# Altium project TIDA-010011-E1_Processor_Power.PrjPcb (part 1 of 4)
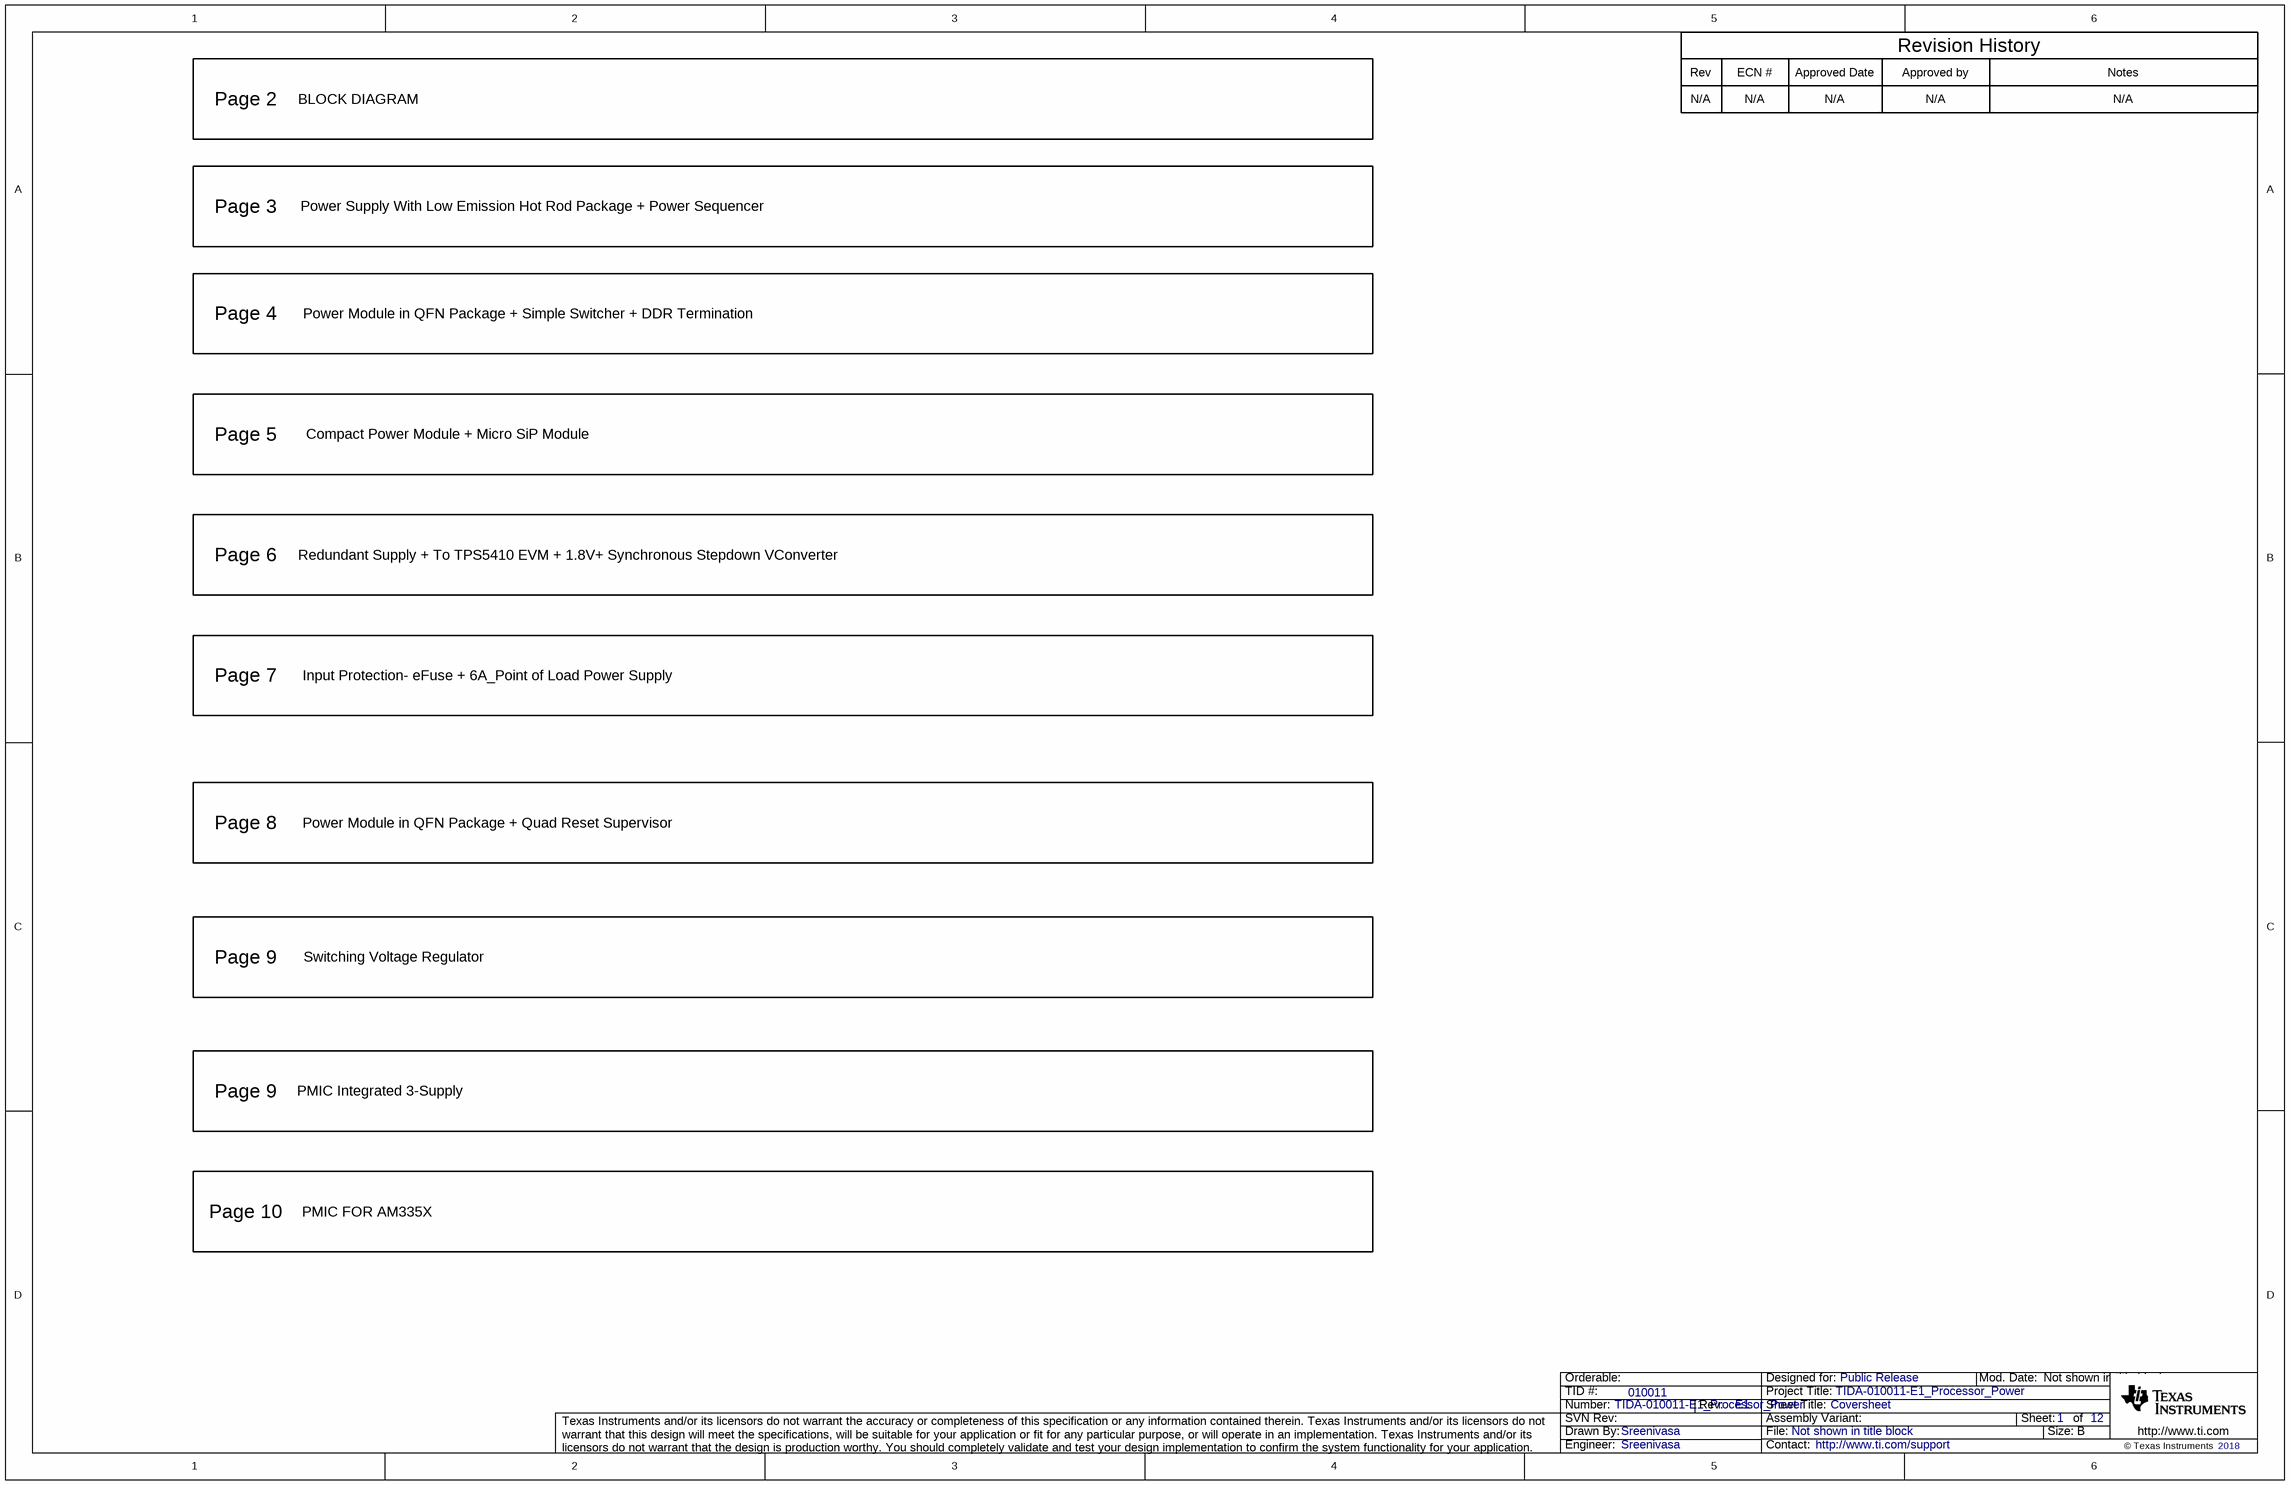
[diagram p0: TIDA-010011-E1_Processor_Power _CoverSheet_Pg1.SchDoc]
CopyrightYear: 2018; PCB_Layout: Avinash N; PCB_Rev: E1; PRJ_Customer: Public Release; PRJ_Engineer: Sreenivasa; PRJ_Number: TIDA-010011-E1_Processor_Power; PRJ_Title: TIDA-010011-E1_Processor_Power; SCH_Rev: E1; TechSupport: http://www.ti.com/support; TID: 010011
12 sheets, 636 parts. Net scope: global (net labels, ports and power ports of the same name join across sheets).
Board file: TIDA-010011-E1_Processor_Power.PcbDoc
Sheets:
  TIDA-010011-E1_Processor_Power _CoverSheet_Pg1.SchDoc
  TIDA-010011-E1_Processor_Power _ Block Diagram_Pg2.SchDoc
  TIDA-010011-E1_Processor_Power _Pg3.SchDoc
  TIDA-010011-E1_Processor_Power _Pg4.SchDoc
  TIDA-010011-E1_Processor_Power _Pg5.SchDoc
  TIDA-010011-E1_Processor_Power _Pg6.SchDoc
  TIDA-010011-E1_Processor_Power _Pg7.SchDoc
  TIDA-010011-E1_Processor_Power _Pg8.SchDoc
  TIDA-010011-E1_Processor_Power _Pg9.SchDoc
  TIDA-010011-E1_Processor_Power _Pg10.SchDoc
  TIDA-010011-E1_Processor_Power _Pg11.SchDoc
  TIDA-010011-E1_Processor_Power _EVM_Hardware_Pg11.SchDoc

## Sheet TIDA-010011-E1_Processor_Power _CoverSheet_Pg1.SchDoc: Coversheet
size 431 x 279 mm; Date: Not shown in title block; ApprovedBy: Not shown in title block; CheckedBy: Not shown in title block; Author: Not shown in title block; CompanyName: Not shown in title block; DrawnBy: Sreenivasa; Engineer: Not shown in title block; Organization: Not shown in title block; Address1: Not shown in title block; Address2: Not shown in title block; Address3: Not shown in title block; Address4: Not shown in title block; DocumentNumber: 1; Revision: Use project parameter SCH_Rev; SheetNumber: 1; SheetTotal: 12; PageSetup: Record=PageOptions¦CenterHorizontal=True¦CenterVertical=True¦PrintScale=1.00¦XCorrection=1.00¦YCorrection=1.00¦PrintKind=0¦BorderSize=5000000¦LeftOffset=0¦BottomOffset=0¦Orientation=2¦PaperLength=1000¦PaperWidth=1000¦Scale=100¦PaperSource=15¦PrintQuality=600¦MediaType=1¦DitherType=10¦PaperKind=Letter¦PrintScaleMode=1

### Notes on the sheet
- Page 2
- BLOCK DIAGRAM
- Rev
- N/A
- ECN #
- Approved Date
- Approved by
- Revision History
- Notes
- Page 3
- Power Supply With Low Emission Hot Rod Package + Power Sequencer
- Page 4
- Power Module in QFN Package + Simple Switcher + DDR Termination
- Page 5
- Compact Power Module + Micro SiP Module
- Page 6
- Redundant Supply + To TPS5410 EVM + 1.8V+ Synchronous Stepdown VConverter
- Page 7
- Input Protection- eFuse + 6A_Point of Load Power Supply
- Page 8
- Power Module in QFN Package + Quad Reset Supervisor
- Page 9
- Switching Voltage Regulator
- PMIC Integrated 3-Supply
- Page 10
- PMIC FOR AM335X

## Sheet TIDA-010011-E1_Processor_Power _ Block Diagram_Pg2.SchDoc: Block Diagram
size 431 x 279 mm; Date: Not shown in title block; ApprovedBy: Not shown in title block; CheckedBy: Not shown in title block; Author: Not shown in title block; CompanyName: Not shown in title block; DrawnBy: Sreenivasa; Engineer: Sreenivasa; Organization: Not shown in title block; Address1: Not shown in title block; Address2: Not shown in title block; Address3: Not shown in title block; Address4: Not shown in title block; DocumentNumber: 1; Revision: Use project parameter SCH_Rev; SheetNumber: 2; SheetTotal: 12; PageSetup: Record=PageOptions¦CenterHorizontal=True¦CenterVertical=True¦PrintScale=1.00¦XCorrection=1.00¦YCorrection=1.00¦PrintKind=0¦BorderSize=5000000¦LeftOffset=0¦BottomOffset=0¦Orientation=2¦PaperLength=1000¦PaperWidth=1000¦Scale=100¦PaperSource=15¦PrintQuality=600¦MediaType=1¦DitherType=10¦PaperKind=Letter¦PrintScaleMode=1
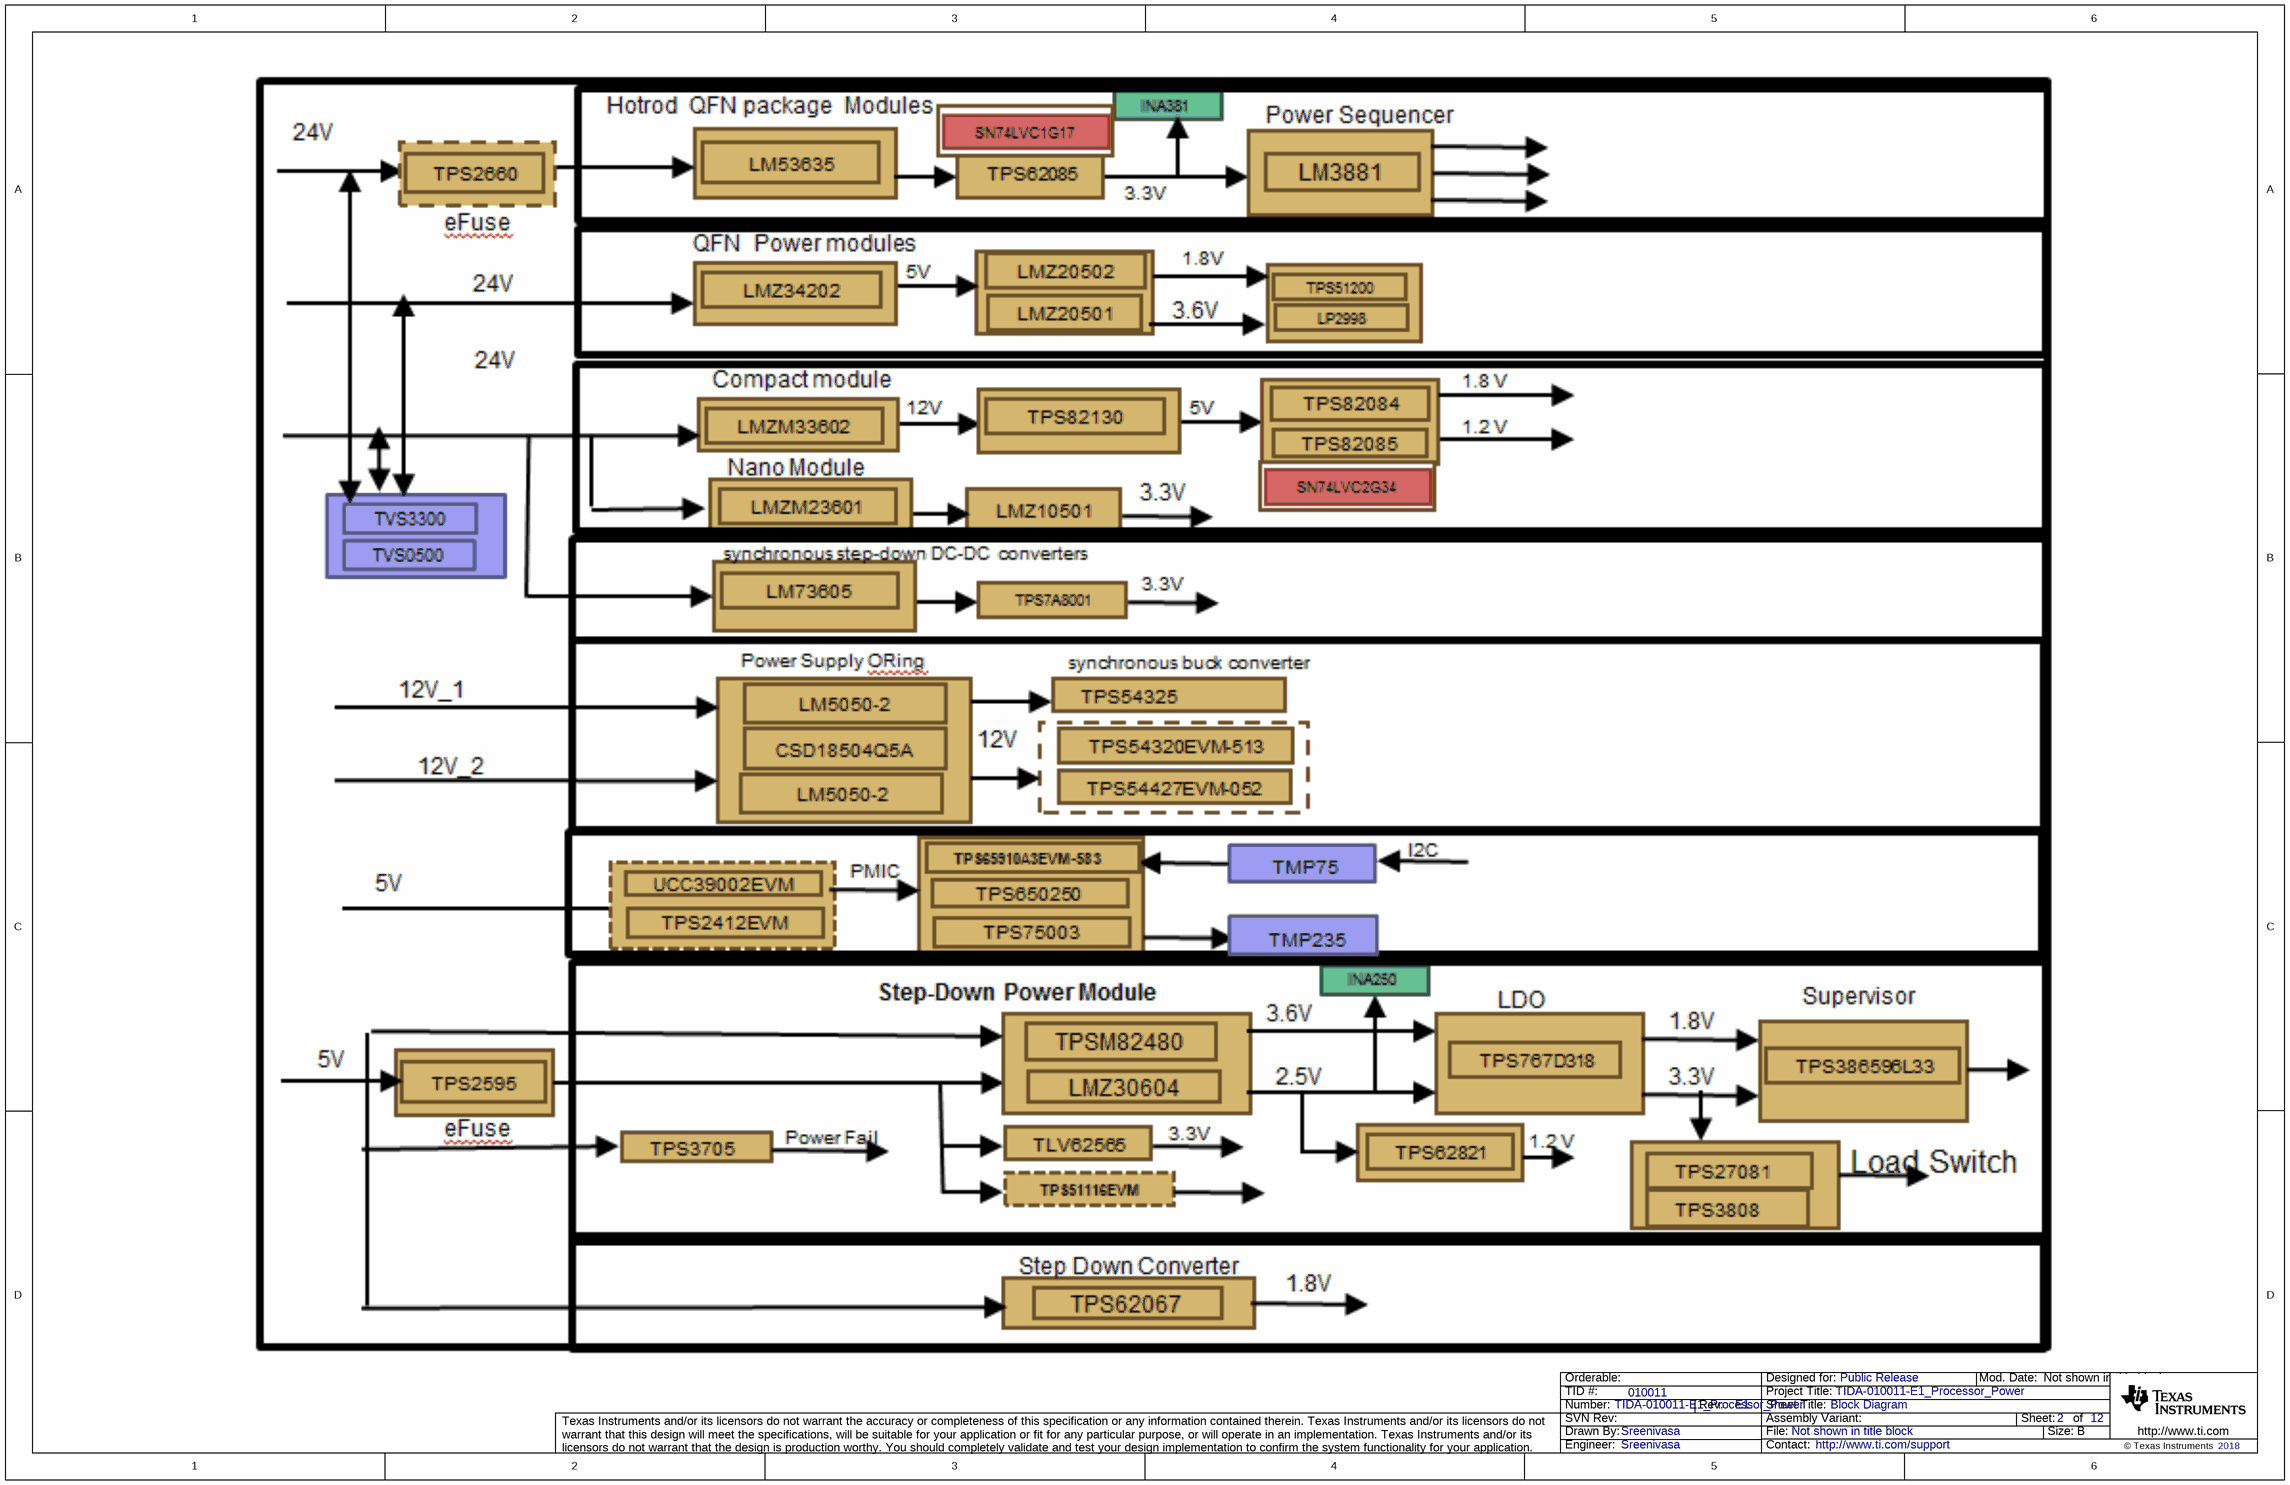
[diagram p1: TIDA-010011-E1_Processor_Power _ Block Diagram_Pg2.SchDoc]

## Sheet TIDA-010011-E1_Processor_Power _Pg3.SchDoc: +24V_HOT RED PACKAGE
size 431 x 279 mm; Date: Not shown in title block; ApprovedBy: Not shown in title block; CheckedBy: Not shown in title block; Author: Not shown in title block; CompanyName: Not shown in title block; DrawnBy: Sreenivasa; Engineer: Not shown in title block; Organization: Not shown in title block; Address1: Not shown in title block; Address2: Not shown in title block; Address3: Not shown in title block; Address4: Not shown in title block; DocumentNumber: 1; Revision: Use project parameter SCH_Rev; SheetNumber: 3; SheetTotal: 12; PageSetup: Record=PageOptions¦CenterHorizontal=True¦CenterVertical=True¦PrintScale=0.62¦XCorrection=1.00¦YCorrection=1.00¦PrintKind=0¦BorderSize=5000000¦LeftOffset=0¦BottomOffset=0¦Orientation=2¦PaperLength=1000¦PaperWidth=1000¦Scale=100¦PaperSource=15¦PrintQuality=600¦MediaType=1¦DitherType=10¦PrintScaleMode=1¦PaperKind=Letter
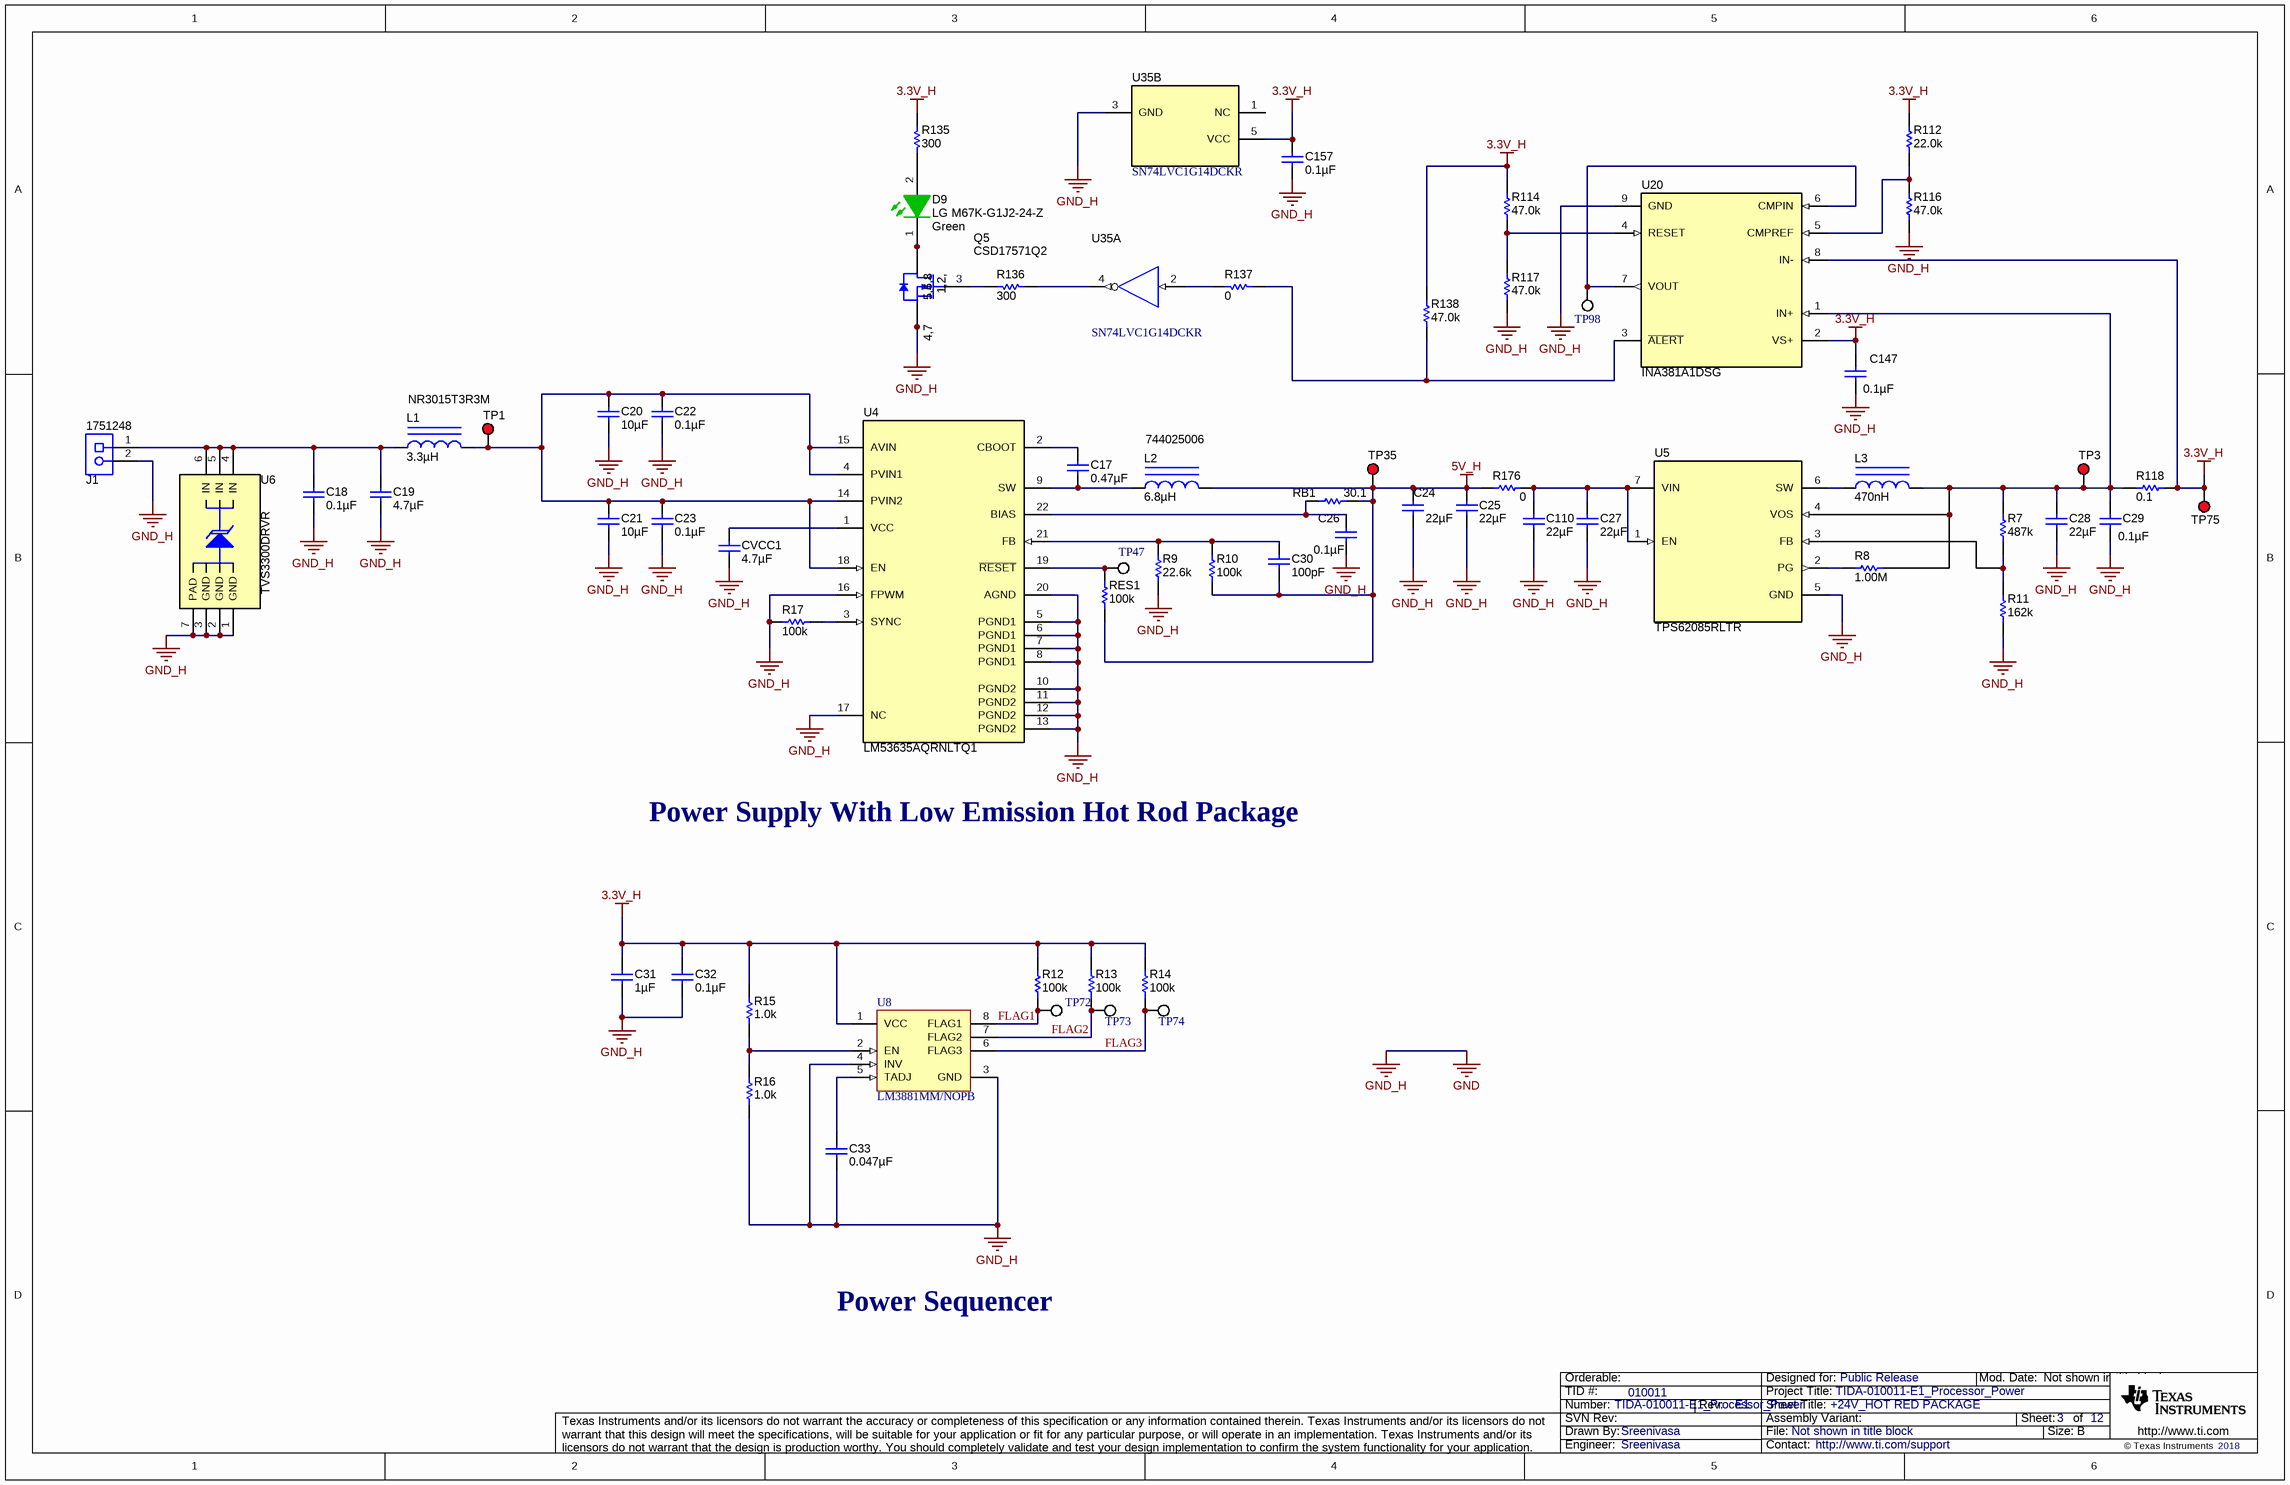
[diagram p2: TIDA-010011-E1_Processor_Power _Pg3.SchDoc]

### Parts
C17  ValueDisplayed: 0.47µF  [0603]  (hidden comment: GCM188R71E474KA64D)
C18  ValueDisplayed: 0.1µF  [0805_HV]  (hidden comment: C2012X7R2A104K125AA)
C19  ValueDisplayed: 4.7µF  [1206]  (hidden comment: C3216X7R1V475K085AC)
C20  ValueDisplayed: 10µF  [1206_180]  (hidden comment: GRM31CR71E106KA12L)
C21  ValueDisplayed: 10µF  [1206_180]  (hidden comment: GRM31CR71E106KA12L)
C22  ValueDisplayed: 0.1µF  [0805_HV]  (hidden comment: C2012X7R2A104K125AA)
C23  ValueDisplayed: 0.1µF  [0805_HV]  (hidden comment: C2012X7R2A104K125AA)
C24  ValueDisplayed: 22µF  [1210_280]  (hidden comment: CGA6P1X7R1C226M250AC)
C25  ValueDisplayed: 22µF  [1210_280]  (hidden comment: CGA6P1X7R1C226M250AC)
C26  ValueDisplayed: 0.1µF  [0603L]  (hidden comment: GRM188R71H104KA93D)
C27  ValueDisplayed: 22µF  [0805_HV]  (hidden comment: JMK212BJ226KG-T)
C28  ValueDisplayed: 22µF  [0805_HV]  (hidden comment: JMK212BJ226KG-T)
C29  ValueDisplayed: 0.1µF  [0603L]  (hidden comment: GRM188R71H104KA93D)
C30  ValueDisplayed: 100pF  [0603]  (hidden comment: 06035A101JAT2A)
C31  ValueDisplayed: 1µF  [0603]  (hidden comment: CL10B105KQ8NNNC)
C32  ValueDisplayed: 0.1µF  [0603]  (hidden comment: 0603ZC104KAT2A)
C33  ValueDisplayed: 0.047µF  [0805_HV]  (hidden comment: 08055C473KAT2A)
C110  ValueDisplayed: 22µF  [0805_HV]  (hidden comment: JMK212BJ226KG-T)
C147  ValueDisplayed: 0.1µF  [0603L]  (hidden comment: GRM188R71H104KA93D)
C157  ValueDisplayed: 0.1µF  [0603]  (hidden comment: GMK107BJ104KAHT)
CVCC1  ValueDisplayed: 4.7µF  [0603]  (hidden comment: CGB3B1X5R1A475K055AC)
D9  LG M67K-G1J2-24-Z  value Green  [LG_M67K_Green]
J1  1751248  [CONN_1751248]
L1  NR3015T3R3M  ValueDisplayed: 3.3µH  [NR3015]
L2  744025006  ValueDisplayed: 6.8µH  [WE-TPC_2828]
L3  ValueDisplayed: 470nH  [VLS2012ET]  (hidden comment: VLS2012ET-R47N)
Q5  CSD17571Q2  [DQK0006C]
R7  ValueDisplayed: 487k  [0402]  (hidden comment: CRCW0402487KFKED)
R8  ValueDisplayed: 1.00M  [0402L]  (hidden comment: RC0402FR-071ML)
R9  ValueDisplayed: 22.6k  [0402]  (hidden comment: CRCW040222K6FKED)
R10  ValueDisplayed: 100k  [0402]  (hidden comment: CRCW0402100KFKED)
R11  ValueDisplayed: 162k  [0603L]  (hidden comment: RC0603FR-07162KL)
R12  ValueDisplayed: 100k  [0805_HV]  (hidden comment: ERJ-6ENF1003V)
R13  ValueDisplayed: 100k  [0805_HV]  (hidden comment: ERJ-6ENF1003V)
R14  ValueDisplayed: 100k  [0805_HV]  (hidden comment: ERJ-6ENF1003V)
R15  ValueDisplayed: 1.0k  [0603]  (hidden comment: CRCW06031K00JNEA)
R16  ValueDisplayed: 1.0k  [0603]  (hidden comment: CRCW06031K00JNEA)
R17  ValueDisplayed: 100k  [0402]  (hidden comment: CRCW0402100KFKED)
R112  ValueDisplayed: 22.0k  [0603]  (hidden comment: ERJ-3EKF2202V)
R114  ValueDisplayed: 47.0k  [0603]  (hidden comment: RG1608P-473-B-T5)
R116  ValueDisplayed: 47.0k  [0603]  (hidden comment: RG1608P-473-B-T5)
R117  ValueDisplayed: 47.0k  [0603]  (hidden comment: RG1608P-473-B-T5)
R118  ValueDisplayed: 0.1  [0805_HV]  (hidden comment: ERJ-6RSJR10V)
R135  ValueDisplayed: 300  [0603]  (hidden comment: CRCW0603300RJNEA)
R136  ValueDisplayed: 300  [0603]  (hidden comment: CRCW0603300RJNEA)
R137  ValueDisplayed: 0  [0603]  (hidden comment: RMCF0603ZT0R00)
R138  ValueDisplayed: 47.0k  [0603]  (hidden comment: RG1608P-473-B-T5)
R176  ValueDisplayed: 0  [0805_HV]  (hidden comment: CRCW08050000Z0EA)
RB1  ValueDisplayed: 30.1  [0402]  (hidden comment: CRCW040230R1FKED)
RES1  ValueDisplayed: 100k  [0603]  (hidden comment: RG1608P-104-B-T5)
TP1  (no value)  [Keystone5000]
TP3  (no value)  [Keystone5000]
TP35  (no value)  [Keystone5000]
TP47  5002  [Keystone5002]  (value not drawn)
TP72  5002  [Keystone5002]  (value not drawn)
TP73  5002  [Keystone5002]  (value not drawn)
TP74  5002  [Keystone5002]  (value not drawn)
TP75  (no value)  [Keystone5000]
TP98  5002  [Keystone5002]  (value not drawn)
U4  LM53635AQRNLTQ1  [RNL0022A_NV]
U5  TPS62085RLTR  [RLT0007A]
U6  TVS3300DRVR  [DRV0006A]
U8  LM3881MM/NOPB  [MUA08A_N]
U20  INA381A1DSG  [DSG0008A]
U35  SN74LVC1G14DCKR  [DCK0005A_N]  (parts A,B of 2)

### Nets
3.3V_H: C31.1 C32.1 C147.1 C157.1 R12.2 R13.2 R14.2 R15.2 R112.2 R114.1 R118.1 R135.2 R138.1 TP75.1 U8.1(VCC) U20.2(VS+) U20.8(IN-) U35.5(VCC)
5V_H: C24.1 C25.1 C30.2 L2.2 R10.1 R176.2 RB1.2 RES1.1 TP35.1
GND: C18.2 C19.2 C20.2 C21.2 C22.2 C23.2 C24.2 C25.2 C26.2 C27.2 C28.2 C29.2 C31.2 C32.2 C33.2 C110.2 C147.2 C157.2 CVCC1.2 J1.2 Q5.4(S) Q5.7(S) R9.1 R11.1 R16.1 R17.2 R116.1 R117.1 U4.5(PGND1) U4.6(PGND1) U4.7(PGND1) U4.8(PGND1) U4.10(PGND2) U4.11(PGND2) U4.12(PGND2) U4.13(PGND2) U4.16(FPWM) U4.17(NC) U4.20(AGND) U5.5(GND) U6.1(GND) U6.2(GND) U6.3(GND) U6.7(PAD) U8.3(GND) U8.4(INV) U20.9(GND) U35.3(GND)  [also labelled GND_H]
FLAG1: R12.1 TP72.1 U8.8(FLAG1)
FLAG2: R13.1 TP73.1 U8.7(FLAG2)
FLAG3: R14.1 TP74.1 U8.6(FLAG3)
NetC17_1: C17.1 U4.2(CBOOT)
NetC17_2: C17.2 L2.1 U4.9(SW)
NetC18_1: C18.1 C19.1 J1.1 L1.1 U6.4(IN) U6.5(IN) U6.6(IN)
NetC20_1: C20.1 C21.1 C22.1 C23.1 L1.2 TP1.1 U4.4(PVIN1) U4.14(PVIN2) U4.15(AVIN) U4.18(EN)
NetC26_1: C26.1 RB1.1 U4.22(BIAS)
NetC27_1: C27.1 C110.1 R176.1 U5.1(EN) U5.7(VIN)
NetC28_1: C28.1 C29.1 L3.2 R7.2 R8.2 R118.2 TP3.1 U5.4(VOS) U20.1(IN+)
NetC30_1: C30.1 R9.2 R10.2 U4.21(FB)
NetC33_1: C33.1 U8.5(TADJ)
NetCVCC1_1: CVCC1.1 U4.1(VCC)
NetD9_1: D9.1(K) Q5.1(D) Q5.2(D) Q5.5(D) Q5.6(D) Q5.8(D)
NetD9_2: D9.2(A) R135.1
NetL3_1: L3.1 U5.6(SW)
NetQ5_3: Q5.3(G) R136.1
NetR7_1: R7.1 R11.2 U5.3(FB)
NetR8_1: R8.1 U5.2(PG)
NetR15_1: R15.1 R16.2 U8.2(EN)
NetR17_1: R17.1 U4.3(SYNC)
NetR112_1: R112.1 R116.2 U20.5(CMPREF)
NetR114_2: R114.2 R117.2 U20.4(RESET)
NetR136_2: R136.2 U35.4(Y)
NetR137_1: R137.1 R138.2 U20.3(~{ALERT})
NetR137_2: R137.2 U35.2(A)
NetRES1_2: RES1.2 TP47.1 U4.19(~{RESET})
NetTP98_1: TP98.1 U20.6(CMPIN) U20.7(VOUT)

Not connected (* = marked no-connect by the designer): U35 1(NC)

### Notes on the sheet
- Power Supply With Low Emission Hot Rod Package
- Power Sequencer

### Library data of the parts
C17 = GCM188R71E474KA64D: CAP, CERM, 0.47 µF, 25 V, +/- 10%, X7R, AEC-Q200 Grade 1, 0603; Manufacturer: MuRata; Polarized: N; CompType: Capacitor; Value: 0.47uF; U/M: EA; Cap_F: 0.00000047; Tolerance_%: 10; Value1: Unknown; VDC_V: 25; Value2: 25V; TaMin_C: -55; TaMax_C: 125; SizeArea_mm2: 1.28; SizeAreaWB_mm2: 4.68; SizeX_mm: 1.6; SizeY_mm: 0.8; SizeZ_mm: 1; AEC Category: Q200; AEC Qualified: Y
C18 C22 C23 = C2012X7R2A104K125AA: CAP, CERM, 0.1 µF, 100 V, +/- 10%, X7R, 0805; Manufacturer: TDK; Polarized: N; CompType: Capacitor; Value: 0.1uF; U/M: EA; Cap_F: 0.0000001; Tolerance_%: 10; ESR_ohm: 0.020726; Value1: 0.020726 ohm; VDC_V: 100; Value2: 100V; IRMS_A: 1.456; TaMin_C: -55; TaMax_C: 125; Cap_Case: 0805; SizeArea_mm2: 2.5; SizeAreaWB_mm2: 6.75; SizeX_mm: 2; SizeY_mm: 1.25; SizeZ_mm: 1.45; AEC Category: Q200
C19 = C3216X7R1V475K085AC: CAP, CERM, 4.7 µF, 35 V, +/- 10%, X7R, 1206; Manufacturer: TDK; Polarized: N; CompType: Capacitor; Value: 4.7uF; U/M: EA; Cap_F: 0.0000047; Tolerance_%: 10; ESR_ohm: 0.003785; Value1: 0.003785 ohm; VDC_V: 35; Value2: 35V; IRMS_A: 3.73011; TaMin_C: -55; TaMax_C: 125; SizeArea_mm2: 5.12; SizeAreaWB_mm2: 10.92; SizeX_mm: 3.2; SizeY_mm: 1.6; SizeZ_mm: 1.35; AEC Category: Q200
C20 C21 = GRM31CR71E106KA12L: CAP, CERM, 10 µF, 25 V, +/- 10%, X7R, 1206; Manufacturer: MuRata; Polarized: N; CompType: Capacitor; Value: 10uF; U/M: EA; Cap_F: 0.00001; Tolerance_%: 10; Value1: Unknown; VDC_V: 25; Value2: 25V; TaMin_C: -55; TaMax_C: 125; Cap_Case: 2220; SizeArea_mm2: 5.12; SizeAreaWB_mm2: 10.92; SizeX_mm: 3.2; SizeY_mm: 1.6; SizeZ_mm: 1.8; AEC Category: Q200
C24 C25 = CGA6P1X7R1C226M250AC: CAP, CERM, 22 µF, 16 V, +/- 20%, X7R, AEC-Q200 Grade 1, 1210; Manufacturer: TDK; Polarized: N; CompType: Capacitor; Value: 22uF; U/M: EA; Cap_F: 0.000022; Tolerance_%: 20; ESR_ohm: 0.002582; Value1: 0.002582 ohm; VDC_V: 16; Value2: 16V; IRMS_A: 4.57562; TaMin_C: -55; TaMax_C: 125; SizeArea_mm2: 8; SizeAreaWB_mm2: 14.7; SizeX_mm: 3.2; SizeY_mm: 2.5; SizeZ_mm: 2.8; AEC Category: Q200; AEC Qualified: Y; AEC Grade: 1
C26 C29 C147 = GRM188R71H104KA93D: CAP, CERM, 0.1 µF, 50 V, +/- 10%, X7R, 0603; Manufacturer: MuRata; Polarized: N; CompType: Capacitor; Value: 0.1uF; U/M: EA; Cap_F: 0.0000001; Tolerance_%: 10; Value1: Unknown; VDC_V: 50; Value2: 50V; TaMin_C: -55; TaMax_C: 125; Cap_Case: 0603
C27 C28 C110 = JMK212BJ226KG-T: CAP, CERM, 22 µF, 6.3 V,+/- 10%, X5R, 0805; Manufacturer: Taiyo Yuden; Polarized: N; CompType: Capacitor; Value: 22uF; U/M: EA; Cap_F: 0.000022; Tolerance_%: 10; ESR_ohm: 0.002; Value1: 0.002 ohm; VDC_V: 6.3; Value2: 6.3V; TaMin_C: -55; TaMax_C: 85; Cap_Case: 0805; AEC Category: Q200; SizeArea_mm2: 2.5; SizeAreaWB_mm2: 6.75; SizeX_mm: 2; SizeY_mm: 1.25; SizeZ_mm: 1.45; Green_Lifecycle: Not Set; Green_REACh: Incomplete
C30 = 06035A101JAT2A: CAP, CERM, 100 pF, 50 V,+/- 5%, C0G/NP0, 0603; Manufacturer: AVX; Polarized: N; CompType: Capacitor; Value: 100pF; U/M: EA; Cap_F: 0.0000000001; Tolerance_%: 5; ESR_ohm: 0.119; Value1: 0.119 ohm; VDC_V: 50; Value2: 50V; TaMin_C: -55; TaMax_C: 125; SizeArea_mm2: 1.28; SizeAreaWB_mm2: 4.68; SizeX_mm: 1.6; SizeY_mm: 0.8; SizeZ_mm: 1; AEC Category: Q200; Green_Lifecycle: Active; Green_REACh: Passed
C31 = CL10B105KQ8NNNC: CAP, CERM, 1 µF, 6.3 V, +/- 10%, X7R, 0603; Manufacturer: Samsung Electro-Mechanics; Polarized: N; CompType: Capacitor; Value: 1uF; U/M: EA; Cap_F: 0.000001; Tolerance_%: 10; Value1: Unknown; VDC_V: 6.3; Value2: 6.3V; TaMin_C: -55; TaMax_C: 125; SizeArea_mm2: 1.28; SizeAreaWB_mm2: 4.68; SizeX_mm: 1.6; SizeY_mm: 0.8; SizeZ_mm: 1; AEC Category: Q200
C32 = 0603ZC104KAT2A: CAP, CERM, 0.1 µF, 10 V, +/- 10%, X7R, 0603; Manufacturer: AVX; Polarized: N; CompType: Capacitor; Value: 0.1uF; U/M: EA; Cap_F: 0.0000001; Tolerance_%: 10; Value1: Unknown; Value2: 10V; TaMin_C: -55; TaMax_C: 125; SizeArea_mm2: 1.28; SizeAreaWB_mm2: 4.68; SizeX_mm: 1.6; SizeY_mm: 0.8; SizeZ_mm: 1; AEC Category: Q200
C33 = 08055C473KAT2A: CAP, CERM, 0.047 µF, 50 V,+/- 10%, X7R, 0805; Manufacturer: AVX; Polarized: N; CompType: Capacitor; Value: 0.047uF; U/M: EA; Cap_F: 0.000000047; Tolerance_%: 10; ESR_ohm: 0.035; Value1: 0.035 ohm; VDC_V: 50; Value2: 50V; TaMin_C: -55; TaMax_C: 125; Cap_Case: 0805; SizeArea_mm2: 2.5; SizeAreaWB_mm2: 6.75; SizeX_mm: 2; SizeY_mm: 1.25; SizeZ_mm: 1.45; AEC Category: Q200; Green_Lifecycle: Active; Green_REACh: Passed
C157 = 06033C104JAT2A: 0.1µF ±10% 35V Ceramic Capacitor X5R 0603; Manufacturer: Taiyo Yuden; Polarized: N; Value: 0.1uF; U/M: EA; Cap_F: 0.0000001; Tolerance_%: 5; ESR_ohm: 0.05; Value1: 0.05 ohm; VDC_V: 25; Value2: 25V; TempCo: X7R; TaMin_C: -55; TaMax_C: 125; SizeArea_mm2: 1.28; SizeAreaWB_mm2: 4.68; SizeX_mm: 1.6; SizeY_mm: 0.8; SizeZ_mm: 1; AEC Category: Q200
CVCC1 = CGB3B1X5R1A475K055AC: CAP, CERM, 4.7 µF, 10 V,+/- 10%, X5R, 0603; Manufacturer: TDK; Polarized: N; CompType: Capacitor; Value: 4.7uF; U/M: EA; Cap_F: 0.0000047; Tolerance_%: 10; Value2: 10V; TaMin_C: -55; TaMax_C: 85; SizeArea_mm2: 1.28; SizeAreaWB_mm2: 4.68; SizeX_mm: 1.6; SizeY_mm: 0.8; SizeZ_mm: 1; AEC Category: Q200; Green_Lifecycle: Active; Green_REACh: Passed
D9 = LG M67K-G1J2-24-Z: LED, Green, SMD; Manufacturer: OSRAM; SymbolCreator: Altium; Type: AlInGaP; Vf_V: 1.8; Value2: 1.8V; Io_A: 0.002; Vr_V: 12; Tjmax_C: 125; Value1: W; Angle: 120; U/M: EA
J1 = 1751248: Conn Term Block, 2POS, 3.5mm, TH; Manufacturer: Phoenix Contact; CompType: Terminal Block; SymbolCreator: a0412235
L1 = NR3015T3R3M: Inductor, Wirewound, Ferrite, 3.3 µH, 1.21 A, 0.096 ohm, AEC-Q200 Grade 2, SMD; Manufacturer: Taiyo Yuden; Value: 3.3uH; Imax_A: 1.21; DCR_ohm: 0.096; Value2: 1.21A; Ind_H: 3.3E-6; Irms: 1.23A @ 40C rise; Isat: 1.21A @ 30% inductance drop; SizeAreaWB_mm2: 16; SizeArea_mm2: 9; SizeX_mm: 3; SizeZ_mm: 1.5; AEC Category: Q200; AEC Qualified: Y; AEC Grade: 2
L2 = 744025006: Inductor, Shielded Drum Core, Ferrite, 6.8 µH, 1.1 A, 0.142 ohm, SMD; Manufacturer: Wurth Elektronik; Value: 6.8uH; Ind_H: 6.8E-6; Imax_A: 1.1; Irms: 1.1A @ 40C rise; Isat: 1.3A @ 35% inductance drop; DCR_ohm: 0.142; Value2: 1.1A; SizeAreaWB_mm2: 14.44; SizeArea_mm2: 7.84; SizeX_mm: 2.8; SizeZ_mm: 3; AEC Category: Q200
L3 = VLS2012ET-R47N: Inductor, Shielded Drum Core, Ferrite, 470 nH, 2 A, 0.059 ohm, SMD; Manufacturer: TDK; Value: 470nH; Ind_H: 470.0E-9; Imax_A: 2; Irms: 2A @ 40C rise; Isat: 2.25A @ 30% inductance drop; DCR_ohm: 0.059; Value2: 2A; AEC Category: Q200
Q5 = CSD17571Q2: MOSFET, N-CH, 30 V, 22 A, DQK0006C (WSON-6); Manufacturer: Texas Instruments; Alternate Manufacturer: None; U/M: EA; ChType: N; Value: 30V; VdsMax_V: 30; Value1: 0.029 ohm; Rdson45_ohm: 0.029; Value2: 2.4 nC; QgTyp_nC: 2.4; Vgs_V: 20; IdsMax_A: 22; SizeAreaWB_mm2: 9; SizeArea_mm2: 4; SizeX_mm: 2; SizeZ_mm: 0.8; AEC Category: Q101
R7 = CRCW0402487KFKED: RES, 487 k, 1%, 0.063 W, 0402; Manufacturer: Vishay-Dale; CompType: Resistor; Value: 487k; Res_ohm: 487000; Tolerance_%: 1; Power_W: 0.063; Value2: 0.063W; VDC_V: 50; TempCo: 100 ppm/C; SizeArea_mm2: 0.5; SizeZ_mm: 0.6; EIA_Code: E96; U/M: EA; AEC Category: Q200; Green_Lifecycle: Active; Green_REACh: Passed
R8 = RC0402FR-071ML: RES, 1.00 M, 1%, 0.063 W, 0402; Manufacturer: Yageo America; CompType: Resistor; Value: 1.00Meg; Res_ohm: 1000000; Value_Code: 1M00; Tolerance_%: 1; Power_W: 0.063; Value2: 0.063W; TempCo: 100 ppm/C; EIA_Code: E96; U/M: EA; AEC Category: Q200; SizeArea_mm2: 0.5; SizeZ_mm: 0.6; Green_Lifecycle: Active; Green_REACh: Passed
R9 = CRCW040222K6FKED: RES, 22.6 k, 1%, 0.063 W, 0402; Manufacturer: Vishay-Dale; CompType: Resistor; Value: 22.6k; Res_ohm: 22600; Value_Code: 22k6; Tolerance_%: 1; Power_W: 0.063; Value2: 0.063W; VDC_V: 50; TempCo: 100 ppm/C; SizeArea_mm2: 0.5; SizeZ_mm: 0.6; EIA_Code: E96; U/M: EA; AEC Category: Q200
R10 R17 = CRCW0402100KFKED: RES, 100 k, 1%, 0.063 W, 0402; Manufacturer: Vishay-Dale; CompType: Resistor; Value: 100k; Res_ohm: 100000; Tolerance_%: 1; Power_W: 0.063; Value2: 0.063W; VDC_V: 50; TempCo: 100 ppm/C; SizeArea_mm2: 0.5; SizeZ_mm: 0.6; EIA_Code: E96; U/M: EA; AEC Category: Q200
R11 = RC0603FR-07162KL: RES, 162 k, 1%, 0.1 W, 0603; Manufacturer: Yageo America; CompType: Resistor; Value: 162k; Res_ohm: 162000; Tolerance_%: 1; Power_W: 0.1; Value2: 0.1W; VDC_V: 150; TempCo: 200 ppm/C; EIA_Code: E96; U/M: EA; AEC Category: Q200; SizeArea_mm2: 1.28; SizeX_mm: 1.6; SizeY_mm: 0.8; Green_Lifecycle: Active; Green_REACh: Passed
R12-R14 = ERJ-6ENF1003V: RES, 100 k, 1%, 0.125 W, 0805; Manufacturer: Panasonic; CompType: Resistor; Value: 100k; Res_ohm: 100000; Tolerance_%: 1; Power_W: 0.125; Value2: 0.125W; TempCo: 100 ppm/C; SizeArea_mm2: 2.5; SizeX_mm: 2; SizeY_mm: 1.25; SizeZ_mm: 1.45; EIA_Code: E96; U/M: EA; AEC Category: Q200
R15 R16 = CRCW06031K00JNEA: RES, 1.0 k, 5%, 0.1 W, 0603; Manufacturer: Vishay-Dale; CompType: Resistor; Value: 1.0k; Res_ohm: 1000; Value_Code: 1k00; Tolerance_%: 5; Power_W: 0.1; Value2: 0.1W; VDC_V: 75; TempCo: 200 ppm/C; SizeArea_mm2: 1.28; SizeX_mm: 1.6; SizeY_mm: 0.8; SizeZ_mm: 1; EIA_Code: E24; U/M: EA; AEC Category: Q200; Green_Lifecycle: Active; Green_REACh: Passed
R112 = ERJ-3EKF2202V: RES, 22.0 k, 1%, 0.1 W, AEC-Q200 Grade 0, 0603; Manufacturer: Panasonic; CompType: Resistor; Value: 22.0k; Res_ohm: 22000; Value_Code: 22k0; Tolerance_%: 1; Power_W: 0.1; Value2: 0.1W; VDC_V: 50; TempCo: 100 ppm/C; SizeArea_mm2: 1.28; SizeX_mm: 1.6; SizeY_mm: 0.8; U/M: EA; AEC Category: Q200; AEC Qualified: Y; AEC Grade: 0; Green_Lifecycle: Active; Green_REACh: Passed
R114 R116 R117 R138 = RG1608P-473-B-T5: RES, 47.0 k, 0.1%, 0.1 W, 0603; Manufacturer: Susumu Co Ltd; CompType: Resistor; Value: 47.0k; Res_ohm: 47000; Value_Code: 47k0; Tolerance_%: 0.1; Value2: 0.1W; VDC_V: 75; TempCo: 25 ppm/C; SizeArea_mm2: 1.28; SizeX_mm: 1.6; SizeY_mm: 0.8; SizeZ_mm: 1; EIA_Code: E192; U/M: EA; AEC Category: Q200
R118 = ERJ-6RSJR10V: RES, 0.1, 5%, 0.125 W, 0805; Manufacturer: Panasonic; CompType: Resistor; Value: 0.1; Value_Code: R100; Tolerance_%: 5; Power_W: 0.125; Value2: 0.125W; TempCo: 250 ppm/C; SizeArea_mm2: 2.5; SizeX_mm: 2; SizeY_mm: 1.25; SizeZ_mm: 1.45; EIA_Code: E24; U/M: EA; AEC Category: Q200; Green_Lifecycle: Not Set; Green_REACh: Incomplete
R135 R136 = CRCW0603300RJNEA: RES, 300, 5%, 0.1 W, 0603; Manufacturer: Vishay-Dale; CompType: Resistor; Value: 300; Value_Code: 300R; Tolerance_%: 5; Power_W: 0.1; Value2: 0.1W; VDC_V: 75; TempCo: 200 ppm/C; SizeArea_mm2: 1.28; SizeX_mm: 1.6; SizeY_mm: 0.8; SizeZ_mm: 1; EIA_Code: E24; U/M: EA; AEC Category: Q200
R137 = RMCF0603ZT0R00: RES, 0, 1%, 0.1 W, AEC-Q200 Grade 0, 0603; Manufacturer: Stackpole Electronics Inc; CompType: Resistor; Value: 0; Tolerance_%: 1; Power_W: 0.1; Value2: 0.1W; TempCo: ppm/C; SizeArea_mm2: 1.28; SizeX_mm: 1.6; SizeY_mm: 0.8; U/M: EA; AEC Category: Q200; AEC Qualified: Y
R176 = CRCW08050000Z0EA: RES, 0, 5%, 0.125 W, 0805; Manufacturer: Vishay-Dale; CompType: Resistor; Value: 0; Value_Code: 0000; Tolerance_%: 5; Power_W: 0.125; Value2: 0.125W; VDC_V: 150; TempCo: 200 ppm/C; SizeArea_mm2: 2.5; SizeX_mm: 2; SizeY_mm: 1.25; SizeZ_mm: 1.45; EIA_Code: E24; U/M: EA; AEC Category: Q200; Green_Lifecycle: Active; Green_REACh: Passed
RB1 = CRCW040230R1FKED: RES, 30.1, 1%, 0.063 W, 0402; Manufacturer: Vishay-Dale; CompType: Resistor; Value: 30.1; Value_Code: 30R1; Tolerance_%: 1; Power_W: 0.063; Value2: 0.063W; VDC_V: 50; TempCo: 100 ppm/C; EIA_Code: E96; U/M: EA; AEC Category: Q200; SizeArea_mm2: 0.5; SizeZ_mm: 0.6; Green_Lifecycle: Active; Green_REACh: Passed
RES1 = RG1608P-104-B-T5: RES, 100 k, 0.1%, 0.1 W, 0603; Manufacturer: Susumu Co Ltd; CompType: Resistor; Value: 100k; Res_ohm: 100000; Tolerance_%: 0.1; Value2: 0.1W; VDC_V: 75; TempCo: 25 ppm/C; SizeArea_mm2: 1.28; SizeX_mm: 1.6; SizeY_mm: 0.8; SizeZ_mm: 1; EIA_Code: E192; U/M: EA; AEC Category: Q200
TP1 TP3 TP35 TP75 = 5000: Test Point, Miniature, Red, TH; Manufacturer: Keystone; CompType: Test Point Loop; ContactFinish: Silver
TP47 TP72-TP74 TP98 = 5002: Test Point, Miniature, White, TH; Manufacturer: Keystone; CompType: Test Point Loop; ContactFinish: Silver; Green_Lifecycle: Active; Green_REACh: Passed
U4 = LM53635RNL: C REG BUCK ADJ 3.5A SYNC 22VQFN; Manufacturer: Texas Instruments; SymbolCreator: Altium; SizeArea_mm2: 20; SizeAreaWB_mm2: 42; SizeX_mm: 4; SizeY_mm: 5; SizeZ_mm: 0.9; CompType: IC; U/M: EA
U5 = TPS62085RLTR: 3-A Step-Down Converter with Hiccup Short Circuit Protection in 2x2 QFN Package, RLT0007A; Alternate PartNumber: TPS62085RLTT; Manufacturer: Texas Instruments; SymbolCreator: a0411947; CompType: IC; U/M: EA
U6 = CMP-0013424-7: 33-V Precision Surge Protection Clamp, DRV0006A (WSON-6); Manufacturer: Texas Instruments; Alternate PartNumber: TVS3300DRVT; SizeX_mm: 2; CompType: IC; SizeZ_mm: 0.8; SizeArea_mm2: 4; SizeAreaWB_mm2: 9; U/M: EA
U8 = LM3881MM/NOPB: Power Sequencer, 8-pin MSOP, Pb-Free; Manufacturer: Texas Instruments; PackageTopMarking: ZXTT*STBB; PowerWise: N; CompType: MiscPower
U20 = CMP-0065195-3: 26-V, Low Cost, Zero-Drift, Voltage-Output, Current-Shunt Monitor With Integrated Comparator, DSG0008A (WSON-8); Manufacturer: Texas Instruments; SizeZ_mm: 0.8; SizeX_mm: 2.0; SizeArea_mm2: 4.0; CompType: IC; U/M: EA; SizeAreaWB_mm2: 9.0
U35 = CMP-0051641-4: Single Schmitt-Trigger Inverter, DCK0005A (SOT-SC70-5); Manufacturer: Texas Instruments; Alternate PartNumber: SN74LVC1G14DCKT; Output Drive (IOL/IOH)(Max)(mA): 32/-32; Schmitt Trigger: Yes; Logic: Inverting; Bits(#): 1; Rating: Catalog; tpd @ Nom Voltage(Max)(ns): 11,6.5,5.5,5; Voltage(Nom)(V): 1.8,2.5,3.3,5; Output Type: CMOS; VCC(Min)(V): 1.65; ICC @ Nom Voltage(Max)(mA): 0.01; Input Type: CMOS/TTL; F @ Nom Voltage(Max)(Mhz): 150; VCC(Max)(V): 5.5; 3-State Output: No; AEC Category: Q200; AEC Qualified: N; CompType: IC; Green_Lifecycle: Active; Green_REACh: Passed; SizeAreaWB_mm2: 9.3; SizeArea_mm2: 4.2; SizeX_mm: 2.1; SizeY_mm: 2.0; SizeZ_mm: 1.1

## Sheet TIDA-010011-E1_Processor_Power _Pg4.SchDoc: POWER MODULE QFN_NANO
size 431 x 279 mm; Date: Not shown in title block; ApprovedBy: Not shown in title block; CheckedBy: Not shown in title block; Author: Not shown in title block; CompanyName: Not shown in title block; Engineer: Not shown in title block; Organization: Not shown in title block; Address1: Not shown in title block; Address2: Not shown in title block; Address3: Not shown in title block; Address4: Not shown in title block; DocumentNumber: 1; Revision: Use project parameter SCH_Rev; SheetNumber: 4; SheetTotal: 12; PageSetup: Record=PageOptions¦CenterHorizontal=True¦CenterVertical=True¦PrintScale=1.00¦XCorrection=1.00¦YCorrection=1.00¦PrintKind=0¦BorderSize=5000000¦LeftOffset=0¦BottomOffset=0¦Orientation=2¦PaperLength=1000¦PaperWidth=1000¦Scale=100¦PaperSource=15¦PrintQuality=600¦MediaType=1¦DitherType=10¦PaperKind=Letter¦PrintScaleMode=1
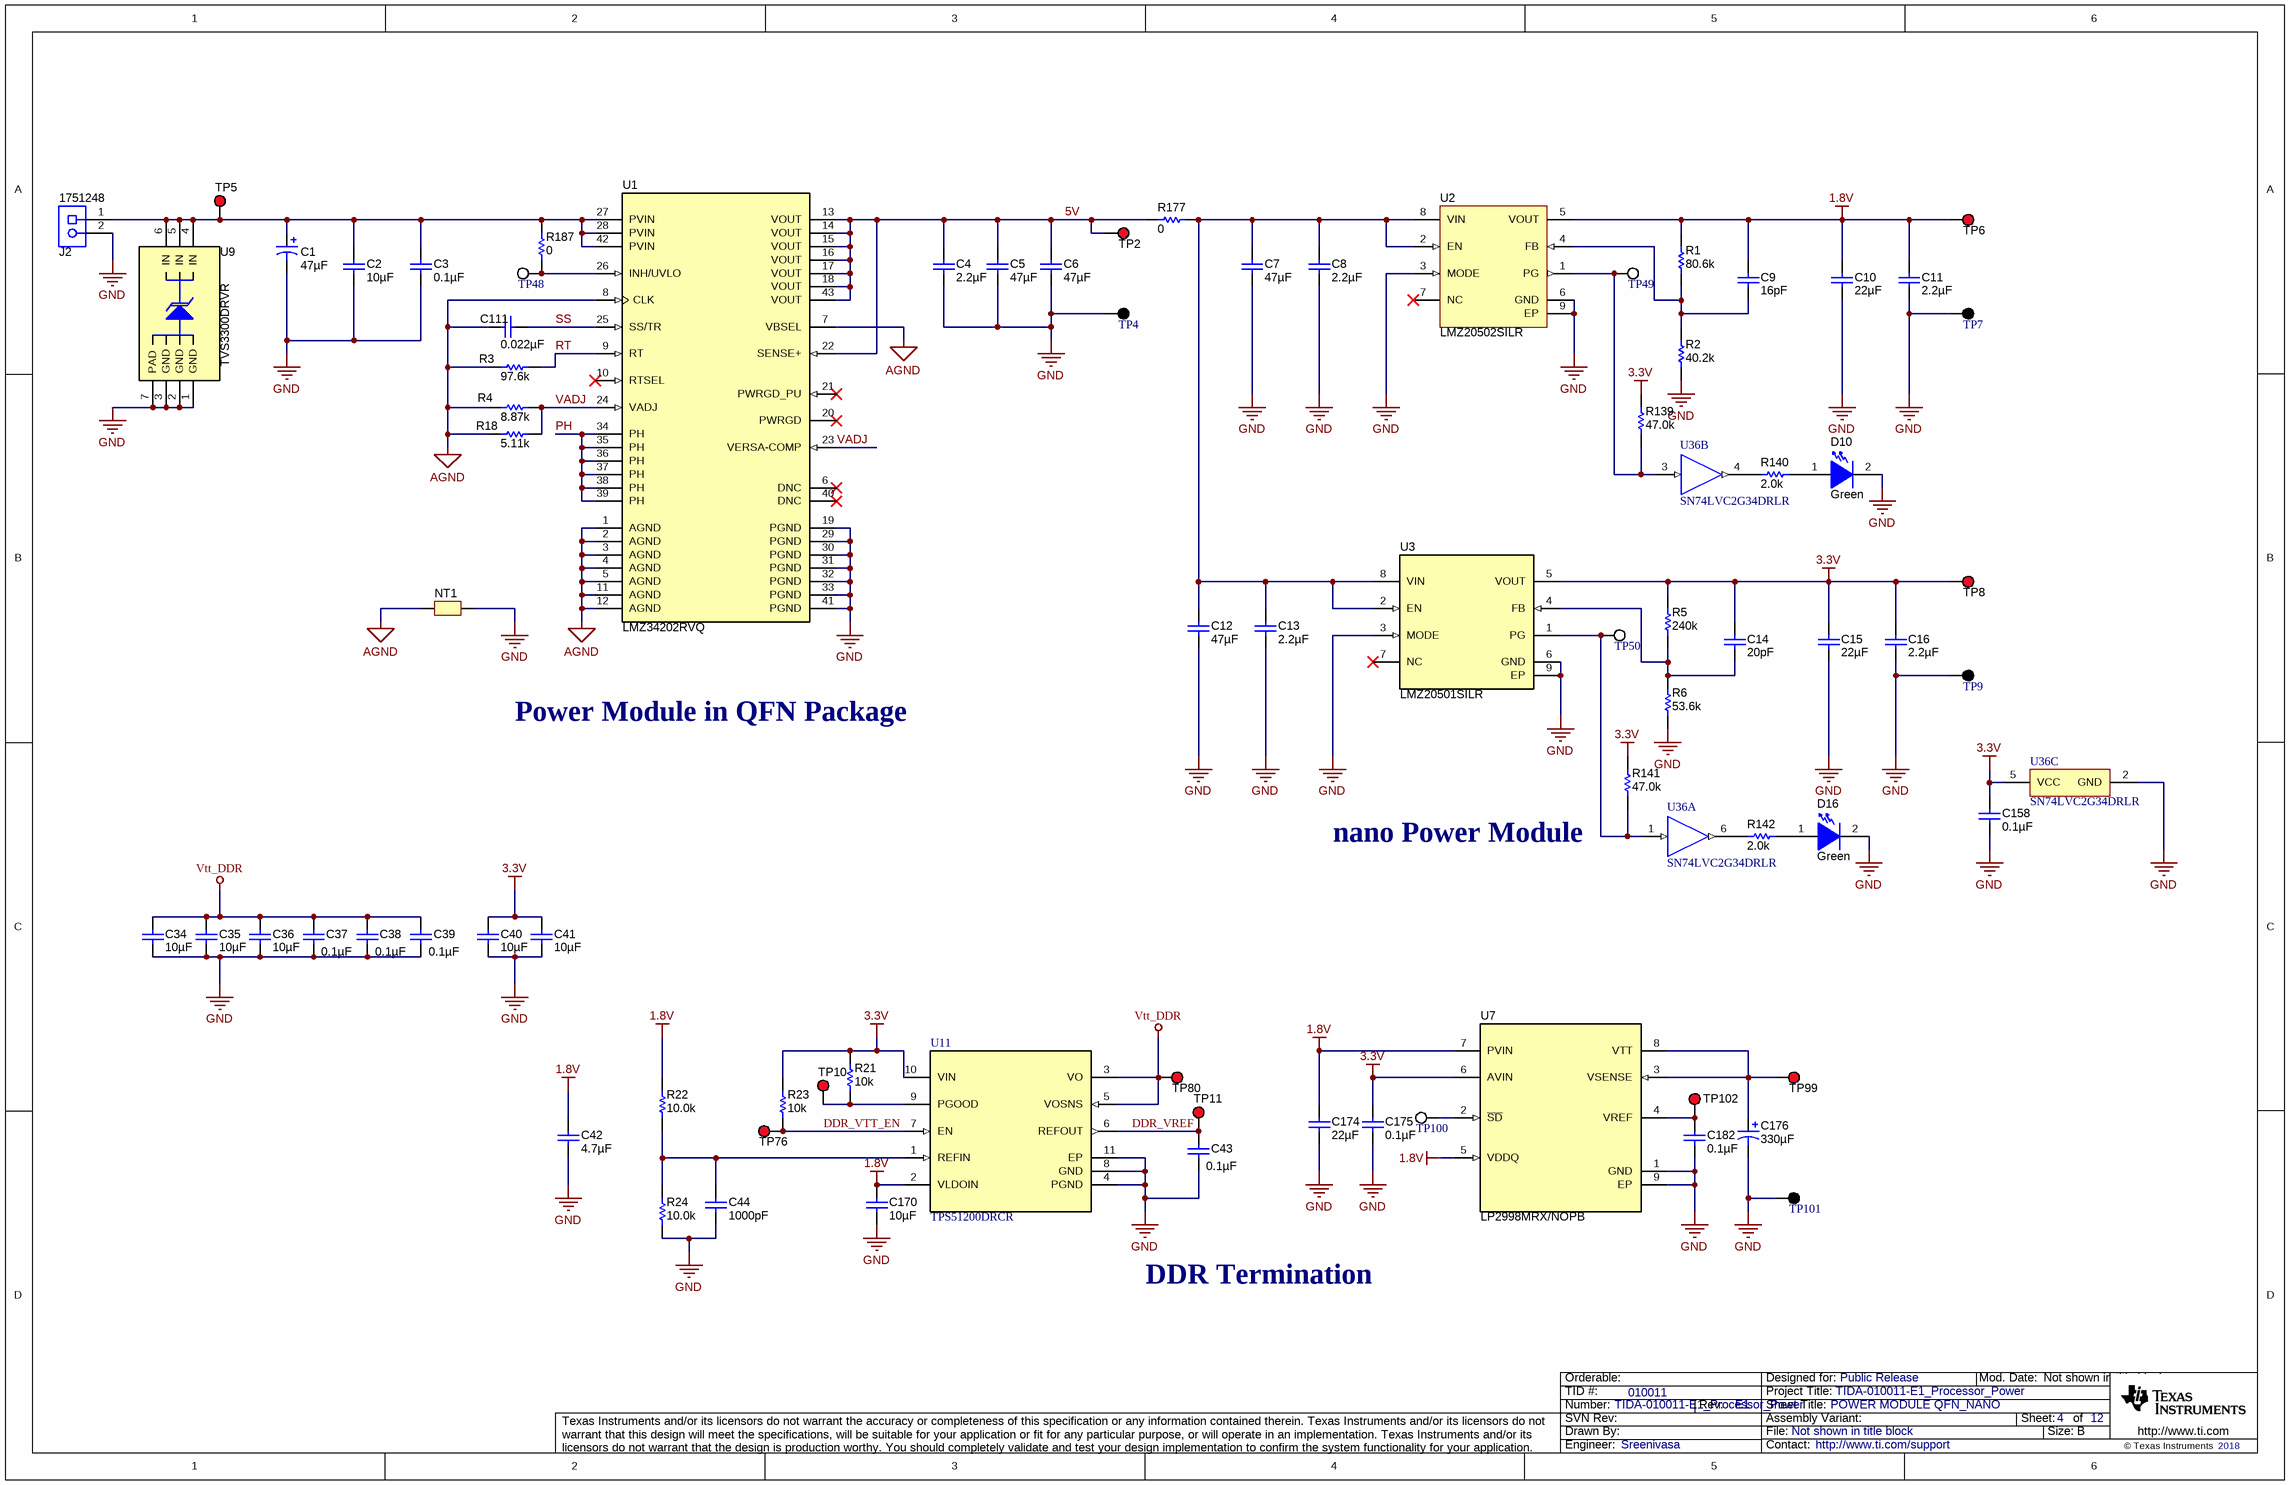
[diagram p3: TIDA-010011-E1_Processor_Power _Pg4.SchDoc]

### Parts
C1  ValueDisplayed: 47µF  [SM_RADIAL_D8]  (hidden comment: EEE-FK1H470XP)
C2  ValueDisplayed: 10µF  [1210]  (hidden comment: GRM32ER71H106KA12L)
C3  ValueDisplayed: 0.1µF  [0603L]  (hidden comment: GRM188R71H104KA93D)
C4  ValueDisplayed: 2.2µF  [0603S]  (hidden comment: GRM188R71A225KE15D)
C5  ValueDisplayed: 47µF  [1206L]  (hidden comment: GRM31CR61A476KE15L)
C6  ValueDisplayed: 47µF  [1206L]  (hidden comment: GRM31CR61A476KE15L)
C7  ValueDisplayed: 47µF  [1206L]  (hidden comment: GRM31CR61A476KE15L)
C8  ValueDisplayed: 2.2µF  [0603S]  (hidden comment: GRM188R71A225KE15D)
C9  ValueDisplayed: 16pF  [0603L]  (hidden comment: GRM1885C1H160JA01D)
C10  ValueDisplayed: 22µF  [1206L]  (hidden comment: GRM31CR71A226KE15L)
C11  ValueDisplayed: 2.2µF  [0603S]  (hidden comment: GRM188R71A225KE15D)
C12  ValueDisplayed: 47µF  [1206L]  (hidden comment: GRM31CR61A476KE15L)
C13  ValueDisplayed: 2.2µF  [0603S]  (hidden comment: GRM188R71A225KE15D)
C14  ValueDisplayed: 20pF  [0603L]  (hidden comment: GRM1885C1H200JA01D)
C15  ValueDisplayed: 22µF  [1206L]  (hidden comment: GRM31CR71A226KE15L)
C16  ValueDisplayed: 2.2µF  [0603S]  (hidden comment: GRM188R71A225KE15D)
C34  ValueDisplayed: 10µF  [0603]  (hidden comment: C1608X5R1E106M080AC)
C35  ValueDisplayed: 10µF  [0603]  (hidden comment: C1608X5R1E106M080AC)
C36  ValueDisplayed: 10µF  [0603]  (hidden comment: C1608X5R1E106M080AC)
C37  ValueDisplayed: 0.1µF  [0603L]  (hidden comment: GRM188R71H104KA93D)
C38  ValueDisplayed: 0.1µF  [0603L]  (hidden comment: GRM188R71H104KA93D)
C39  ValueDisplayed: 0.1µF  [0603L]  (hidden comment: GRM188R71H104KA93D)
C40  ValueDisplayed: 10µF  [0603]  (hidden comment: C1608X5R1E106M080AC)
C41  ValueDisplayed: 10µF  [0603]  (hidden comment: C1608X5R1E106M080AC)
C42  ValueDisplayed: 4.7µF  [0603]  (hidden comment: GRM188R61C475KAAJ)
C43  ValueDisplayed: 0.1µF  [0603L]  (hidden comment: GRM188R71H104KA93D)
C44  ValueDisplayed: 1000pF  [0603]  (hidden comment: C0603C102K3GACTU)
C111  ValueDisplayed: 0.022µF  [0603]  (hidden comment: C0603C223K4RACTU)
C158  ValueDisplayed: 0.1µF  [0603]  (hidden comment: 06033D104KAT2A)
C170  ValueDisplayed: 10µF  [0603]  (hidden comment: C1608X5R1E106M080AC)
C174  ValueDisplayed: 22µF  [1206_180]  (hidden comment: GRM31CR71A226KE15L)
C175  ValueDisplayed: 0.1µF  [0603]  (hidden comment: 06033D104KAT2A)
C176  ValueDisplayed: 330µF  [GX_2TERM]  (hidden comment: EEF-GX0D331R)
C182  ValueDisplayed: 0.1µF  [0603]  (hidden comment: 06033D104KAT2A)
D10  value Green  [LED_LTST-C190_G]  (hidden comment: LTST-C190KGKT)
D16  value Green  [LED_LTST-C190_G]  (hidden comment: LTST-C190KGKT)
J2  1751248  [CONN_1751248]
NT1  Net-Tie  [Net-Tie_10mil]  (value not drawn)  (net tie, no BOM)
R1  ValueDisplayed: 80.6k  [0603L]  (hidden comment: CRCW060380K6FKEA)
R2  ValueDisplayed: 40.2k  [0603L]  (hidden comment: CRCW060340K2FKEA)
R3  ValueDisplayed: 97.6k  [0603L]  (hidden comment: CRCW060397K6FKEA)
R4  ValueDisplayed: 8.87k  [0603L]  (hidden comment: CRCW06038K87FKEA)
R5  ValueDisplayed: 240k  [0603]  (hidden comment: RC0603FR-07240KL)
R6  ValueDisplayed: 53.6k  [0603]  (hidden comment: RC0603FR-0753K6L)
R18  ValueDisplayed: 5.11k  [0603]  (hidden comment: RC0603FR-075K11L)
R21  ValueDisplayed: 10k  [0402]  (hidden comment: CRCW040210K0JNED)
R22  ValueDisplayed: 10.0k  [0402]  (hidden comment: CRCW040210K0FKED)
R23  ValueDisplayed: 10k  [0402]  (hidden comment: CRCW040210K0JNED)
R24  ValueDisplayed: 10.0k  [0402]  (hidden comment: CRCW040210K0FKED)
R139  ValueDisplayed: 47.0k  [0603]  (hidden comment: RC0603FR-0747KL)
R140  ValueDisplayed: 2.0k  [0603]  (hidden comment: CRCW06032K00JNEA)
R141  ValueDisplayed: 47.0k  [0603]  (hidden comment: RC0603FR-0747KL)
R142  ValueDisplayed: 2.0k  [0603]  (hidden comment: CRCW06032K00JNEA)
R177  ValueDisplayed: 0  [0805_HV]  (hidden comment: CRCW08050000Z0EA)
R187  ValueDisplayed: 0  [0805_HV]  (hidden comment: CRCW08050000Z0EA)
TP2  (no value)  [Keystone5000]
TP4  5001  [Keystone5001]  (value not drawn)
TP5  (no value)  [Keystone5000]
TP6  (no value)  [Keystone5000]
TP7  5001  [Keystone5001]  (value not drawn)
TP8  (no value)  [Keystone5000]
TP9  5001  [Keystone5001]  (value not drawn)
TP10  (no value)  [Keystone5000]
TP11  (no value)  [Keystone5000]
TP48  5002  [Keystone5002]  (value not drawn)
TP49  5002  [Keystone5002]  (value not drawn)
TP50  5002  [Keystone5002]  (value not drawn)
TP76  (no value)  [Keystone5000]
TP80  (no value)  [Keystone5000]
TP99  (no value)  [Keystone5000]
TP100  5002  [Keystone5002]  (value not drawn)
TP101  5001  [Keystone5001]  (value not drawn)
TP102  (no value)  [Keystone5000]
U1  LMZ34202RVQ  [RVQ0043A]
U2  LMZ20502SILR  [SIL0008F]
U3  LMZ20501SILR  [SIL0008F]
U7  LP2998MRX/NOPB  [DDA0008A_L]
U9  TVS3300DRVR  [DRV0006A]
U11  TPS51200DRCR  [DRC0010J]
U36  SN74LVC2G34DRLR  [DRL0006A]  (parts A,B,C of 3)

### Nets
1.8V: C9.1 C10.1 C11.1 C42.1 C170.1 C174.2 R1.2 R22.2 TP6.1 U2.5(VOUT) U7.5(VDDQ) U7.7(PVIN) U11.2(VLDOIN)
3.3V: C14.1 C15.1 C16.1 C40.1 C41.1 C158.1 C175.1 R5.2 R21.2 R23.2 R139.2 R141.2 TP8.1 U3.5(VOUT) U7.6(AVIN) U11.10(VIN) U36.5(VCC)
AGND: C111.2 NT1.1 R3.1 R4.1 R18.1 U1.1(AGND) U1.2(AGND) U1.3(AGND) U1.4(AGND) U1.5(AGND) U1.7(VBSEL) U1.8(CLK) U1.11(AGND) U1.12(AGND)
GND: C1.2(-) C2.2 C3.1 C4.2 C5.2 C6.2 C7.2 C8.2 C10.2 C11.2 C12.2 C13.2 C15.2 C16.2 C34.2 C35.2 C36.2 C37.2 C38.2 C39.2 C40.2 C41.2 C42.2 C43.2 C44.2 C158.2 C170.2 C174.1 C175.2 C176.2(-) C182.2 D10.2(K) D16.2(K) J2.2 NT1.2 R2.1 R6.1 R24.1 TP4.1 TP7.1 TP9.1 TP101.1 U1.19(PGND) U1.29(PGND) U1.30(PGND) U1.31(PGND) U1.32(PGND) U1.33(PGND) U1.41(PGND) U2.3(MODE) U2.6(GND) U2.9(EP) U3.3(MODE) U3.6(GND) U3.9(EP) U7.1(GND) U7.9(EP) U9.1(GND) U9.2(GND) U9.3(GND) U9.7(PAD) U11.4(PGND) U11.8(GND) U11.11(EP) U36.2(GND)
Vtt_DDR: C34.1 C35.1 C36.1 C37.1 C38.1 C39.1 TP80.1 U11.3(VO) U11.5(VOSNS)
5V: C4.1 C5.1 C6.1 R177.2 TP2.1 U1.13(VOUT) U1.14(VOUT) U1.15(VOUT) U1.16(VOUT) U1.17(VOUT) U1.18(VOUT) U1.22(SENSE+) U1.43(VOUT)
DDR_VREF: C43.1 TP11.1 U11.6(REFOUT)
DDR_VTT_EN: R23.1 TP76.1 U11.7(EN)
PH: U1.34(PH) U1.35(PH) U1.36(PH) U1.37(PH) U1.38(PH) U1.39(PH)
RT: R3.2 U1.9(RT)
SS: C111.1 U1.25(SS/TR)
VADJ: R4.2 R18.2 U1.23(VERSA-COMP) U1.24(VADJ)
NetC1_1: C1.1(+) C2.1 C3.2 J2.1 R187.1 TP5.1 U1.27(PVIN) U1.28(PVIN) U1.42(PVIN) U9.4(IN) U9.5(IN) U9.6(IN)
NetC7_1: C7.1 C8.1 C12.1 C13.1 R177.1 U2.2(EN) U2.8(VIN) U3.2(EN) U3.8(VIN)
NetC9_2: C9.2 R1.1 R2.2 U2.4(FB)
NetC14_2: C14.2 R5.1 R6.2 U3.4(FB)
NetC44_1: C44.1 R22.1 R24.2 U11.1(REFIN)
NetC176_1: C176.1(+) TP99.1 U7.3(VSENSE) U7.8(VTT)
NetC182_1: C182.1 TP102.1 U7.4(VREF)
NetD10_1: D10.1(A) R140.2
NetD16_1: D16.1(A) R142.2
NetR21_1: R21.1 TP10.1 U11.9(PGOOD)
NetR139_1: R139.1 TP49.1 U2.1(PG) U36.3(2A)
NetR140_1: R140.1 U36.4(2Y)
NetR141_1: R141.1 TP50.1 U3.1(PG) U36.1(1A)
NetR142_1: R142.1 U36.6(1Y)
NetR187_2: R187.2 TP48.1 U1.26(INH/UVLO)
NetTP100_1: TP100.1 U7.2(~{SD})

Not connected (* = marked no-connect by the designer): U1 6(DNC)* 10(RTSEL)* 20(PWRGD)* 21(PWRGD_PU)* 40(DNC)*; U2 7(NC)*; U3 7(NC)*

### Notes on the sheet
- Power Module in QFN Package
- (near R141) nano Power Module
- DDR Termination

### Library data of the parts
C1 = EEE-FK1H470XP: CAP, AL, 47 µF, 50 V, +/- 20%, 0.68 ohm, SMD; Manufacturer: Panasonic; Polarized: Y; CompType: Capacitor; Value: 47uF; U/M: EA; Cap_F: 0.000047; Tolerance_%: 20; VDC_V: 50; Value2: 50V; ESR_ohm: 0.68; IRMS_A: 0.195; TaMin_C: -55; TaMax_C: 105; Cap_Case: D8; AEC Category: Q200
C2 = GRM32ER71H106KA12L: CAP, CERM, 10 µF, 50 V, +/- 10%, X7R, 1210; Manufacturer: MuRata; Polarized: N; CompType: Capacitor; Value: 10uF; U/M: EA; Cap_F: 0.00001; Tolerance_%: 10; Value1: Unknown; VDC_V: 50; Value2: 50V; TaMin_C: -55; TaMax_C: 125
C3 C37-C39 C43 = GRM188R71H104KA93D: as C26 on sheet TIDA-010011-E1_Processor_Power _Pg3
C4 C8 C11 C13 C16 = GRM188R71A225KE15D: CAP, CERM, 2.2 µF, 10 V, +/- 10%, X7R, 0603; Manufacturer: MuRata; Polarized: N; CompType: Capacitor; Value: 2.2uF; U/M: EA; Cap_F: 0.0000022; Tolerance_%: 10; ESR_ohm: 0.009; Value1: 0.009 ohm; Value2: 10V; TaMin_C: -55; TaMax_C: 125; Cap_Case: 0603
C5-C7 C12 = GRM31CR61A476KE15L: CAP, CERM, 47 µF, 10 V, +/- 10%, X5R, 1206; Manufacturer: MuRata; Polarized: N; CompType: Capacitor; Value: 47uF; U/M: EA; Cap_F: 0.000047; Tolerance_%: 10; Value1: Unknown; Value2: 10V; TaMin_C: -55; TaMax_C: 85; Cap_Case: 1206
C9 = GRM1885C1H160JA01D: CAP, CERM, 16 pF, 50 V, +/- 5%, C0G/NP0, 0603; Manufacturer: MuRata; Polarized: N; CompType: Capacitor; Value: 16pF; U/M: EA; Cap_F: 0.000000000016; Tolerance_%: 5; Value1: Unknown; VDC_V: 50; Value2: 50V; TaMin_C: -55; TaMax_C: 125; Cap_Case: 0603; AEC Category: Q200
C10 C15 = GRM31CR71A226KE15L: CAP, CERM, 22 µF, 10 V, +/- 10%, X7R, 1206; Manufacturer: MuRata; Polarized: N; CompType: Capacitor; Value: 22uF; U/M: EA; Cap_F: 0.000022; Tolerance_%: 10; Value1: Unknown; Value2: 10V; TaMin_C: -55; TaMax_C: 125; Cap_Case: 1206
C14 = GRM1885C1H200JA01D: CAP, CERM, 20 pF, 50 V, +/- 5%, C0G/NP0, 0603; Manufacturer: MuRata; Polarized: N; CompType: Capacitor; Value: 20pF; U/M: EA; Cap_F: 0.00000000002; Tolerance_%: 5; Value1: Unknown; VDC_V: 50; Value2: 50V; TaMin_C: -55; TaMax_C: 125; Cap_Case: 0603; AEC Category: Q200
C34-C36 C40 C41 C170 = C1608X5R1E106M080AC: CAP, CERM, 10 µF, 25 V, +/- 20%, X5R, 0603; Manufacturer: TDK; Polarized: N; CompType: Capacitor; Value: 10uF; U/M: EA; Cap_F: 0.00001; Tolerance_%: 20; Value1: Unknown; VDC_V: 25; Value2: 25V; TaMin_C: -55; TaMax_C: 85
C42 = GRM188R61C475KAAJ: CAP, CERM, 4.7 µF, 16 V, +/- 10%, X5R, 0603; Manufacturer: MuRata; Polarized: N; CompType: Capacitor; Value: 4.7uF; U/M: EA; Cap_F: 0.0000047; Tolerance_%: 10; Value1: Unknown; VDC_V: 16; Value2: 16V; TaMin_C: -55; TaMax_C: 85
C44 = C0603C102K3GACTU: CAP, CERM, 1000 pF, 25 V,+/- 10%, C0G/NP0, 0603; Manufacturer: Kemet; Polarized: N; CompType: Capacitor; Value: 1000pF; U/M: EA; Cap_F: 0.000000001; Tolerance_%: 10; ESR_ohm: 0; Value1: 0 ohm; VDC_V: 25; Value2: 25V; TaMin_C: -55; TaMax_C: 125; SizeArea_mm2: 1.28; SizeAreaWB_mm2: 4.68; SizeX_mm: 1.6; SizeY_mm: 0.8; SizeZ_mm: 1; AEC Category: Q200; Green_Lifecycle: Not Set; Green_REACh: Incomplete
C111 = C0603C223K4RACTU: CAP, CERM, 0.022 µF, 16 V,+/- 10%, X7R, 0603; Manufacturer: Kemet; Polarized: N; CompType: Capacitor; Value: 0.022uF; U/M: EA; Cap_F: 0.000000022; Tolerance_%: 10; VDC_V: 16; Value2: 16V; TaMin_C: -55; TaMax_C: 125; SizeArea_mm2: 1.28; SizeAreaWB_mm2: 4.68; SizeX_mm: 1.6; SizeY_mm: 0.8; SizeZ_mm: 1; AEC Category: Q200; Green_Lifecycle: Active; Green_REACh: Passed
C158 C175 C182 = 06033D104KAT2A: CAP, CERM, 0.1 µF, 25 V,+/- 10%, X5R, 0603; Manufacturer: AVX; Polarized: N; CompType: Capacitor; Value: 0.1uF; U/M: EA; Cap_F: 0.0000001; Tolerance_%: 10; ESR_ohm: 0.048; Value1: 0.048 ohm; VDC_V: 25; Value2: 25V; IRMS_A: 0.53; TaMin_C: -55; TaMax_C: 85; SizeArea_mm2: 1.28; SizeAreaWB_mm2: 4.68; SizeX_mm: 1.6; SizeY_mm: 0.8; SizeZ_mm: 1; AEC Category: Q200; Green_Lifecycle: Active; Green_REACh: Passed
C174 = GRM31CR71A226KE15L: CAP, CERM, 22 µF, 10 V,+/- 10%, X7R, 1206; Manufacturer: MuRata; Polarized: N; CompType: Capacitor; Value: 22uF; U/M: EA; Cap_F: 0.000022; Tolerance_%: 10; Value2: 10V; TaMin_C: -55; TaMax_C: 125; Cap_Case: 1206; SizeArea_mm2: 5.12; SizeAreaWB_mm2: 10.92; SizeX_mm: 3.2; SizeY_mm: 1.6; SizeZ_mm: 1.8; AEC Category: Q200; Green_Lifecycle: Active; Green_REACh: Passed
C176 = EEF-GX0D331R: CAP, Aluminum Polymer, 330 µF, 2 V,+/- 20%, 0.003 ohm, SMD_7.3x1.9x4.3mm SMD; Manufacturer: Panasonic; Polarized: Y; CompType: Capacitor; Value: 330uF; U/M: EA; Cap_F: 0.00033; Tolerance_%: 20; VDC_V: 2; Value2: 2V; ESR_ohm: 0.003; IRMS_A: 4; TaMin_C: -40; TaMax_C: 105; Cap_Case: D; AEC Category: Q200
D10 D16 = LTST-C190KGKT: LED, Green, SMD; Manufacturer: Lite-On; Type: AlInGaP; Vf_V: 2; Value2: 2V; Io_A: 0.03; Tjmax_C: 85; Value1: W; U/M: EA
J2 = 1751248: as J1 on sheet TIDA-010011-E1_Processor_Power _Pg3
NT1 = Net-Tie: Single point connection between nets.; SymbolCreator: codlsc
R1 = CRCW060380K6FKEA: RES, 80.6 k, 1%, 0.1 W, 0603; Manufacturer: Vishay-Dale; CompType: Resistor; Value: 80.6k; Res_ohm: 80600; Value_Code: 80k6; Tolerance_%: 1; Power_W: 0.1; Value2: 0.1W; VDC_V: 75; TempCo: 100 ppm/C; EIA_Code: E96; U/M: EA; AEC Category: Q200
R2 = CRCW060340K2FKEA: RES, 40.2 k, 1%, 0.1 W, 0603; Manufacturer: Vishay-Dale; CompType: Resistor; Value: 40.2k; Res_ohm: 40200; Value_Code: 40k2; Tolerance_%: 1; Power_W: 0.1; Value2: 0.1W; VDC_V: 75; TempCo: 100 ppm/C; EIA_Code: E96; U/M: EA; AEC Category: Q200
R3 = CRCW060397K6FKEA: RES, 97.6 k, 1%, 0.1 W, 0603; Manufacturer: Vishay-Dale; CompType: Resistor; Value: 97.6k; Res_ohm: 97600; Value_Code: 97k6; Tolerance_%: 1; Power_W: 0.1; Value2: 0.1W; VDC_V: 75; TempCo: 100 ppm/C; EIA_Code: E96; U/M: EA; AEC Category: Q200
R4 = CRCW06038K87FKEA: RES, 8.87 k, 1%, 0.1 W, 0603; Manufacturer: Vishay-Dale; CompType: Resistor; Value: 8.87k; Res_ohm: 8870; Value_Code: 8k87; Tolerance_%: 1; Power_W: 0.1; Value2: 0.1W; VDC_V: 75; TempCo: 100 ppm/C; EIA_Code: E96; U/M: EA; AEC Category: Q200
R5 = RC0603FR-07240KL: RES, 240 k, 1%, 0.1 W, 0603; Manufacturer: Yageo America; CompType: Resistor; Value: 240k; Res_ohm: 240000; Tolerance_%: 1; Power_W: 0.1; Value2: 0.1W; VDC_V: 150; TempCo: 200 ppm/C; U/M: EA; AEC Category: Q200; SizeArea_mm2: 1.28; SizeX_mm: 1.6; SizeY_mm: 0.8; Green_Lifecycle: Active; Green_REACh: Passed
R6 = RC0603FR-0753K6L: RES, 53.6 k, 1%, 0.1 W, 0603; Manufacturer: Yageo America; CompType: Resistor; Value: 53.6k; Res_ohm: 53600; Value_Code: 53k6; Tolerance_%: 1; Power_W: 0.1; Value2: 0.1W; VDC_V: 150; TempCo: 200 ppm/C; EIA_Code: E96; U/M: EA; AEC Category: Q200; SizeArea_mm2: 1.28; SizeX_mm: 1.6; SizeY_mm: 0.8; Green_Lifecycle: Active; Green_REACh: Passed
R18 = RC0603FR-075K11L: RES, 5.11 k, 1%, 0.1 W, 0603; Manufacturer: Yageo America; CompType: Resistor; Value: 5.11k; Res_ohm: 5110; Value_Code: 5k11; Tolerance_%: 1; Power_W: 0.1; Value2: 0.1W; VDC_V: 150; TempCo: 200 ppm/C; SizeArea_mm2: 1.28; SizeX_mm: 1.6; SizeY_mm: 0.8; EIA_Code: E96; U/M: EA; AEC Category: Q200; Green_Lifecycle: Active; Green_REACh: Passed
R21 R23 = CRCW040210K0JNED: RES, 10 k, 5%, 0.063 W, 0402; Manufacturer: Vishay-Dale; CompType: Resistor; Value: 10k; Res_ohm: 10000; Value_Code: 10k0; Tolerance_%: 5; Power_W: 0.063; Value2: 0.063W; VDC_V: 50; TempCo: 200 ppm/C; EIA_Code: E24; U/M: EA
R22 R24 = CRCW040210K0FKED: RES, 10.0 k, 1%, 0.063 W, 0402; Manufacturer: Vishay-Dale; CompType: Resistor; Value: 10.0k; Res_ohm: 10000; Value_Code: 10k0; Tolerance_%: 1; Power_W: 0.063; Value2: 0.063W; VDC_V: 50; TempCo: 100 ppm/C; EIA_Code: E96; U/M: EA
R139 R141 = RC0603FR-0747KL: RES, 47.0 k, 1%, 0.1 W, 0603; Manufacturer: Yageo America; CompType: Resistor; Value: 47.0k; Res_ohm: 47000; Value_Code: 47k0; Tolerance_%: 1; Power_W: 0.1; Value2: 0.1W; VDC_V: 150; TempCo: 200 ppm/C; SizeArea_mm2: 1.28; SizeX_mm: 1.6; SizeY_mm: 0.8; U/M: EA; AEC Category: Q200; Green_Lifecycle: Active; Green_REACh: Passed
R140 R142 = CRCW06032K00JNEA: RES, 2.0 k, 5%, 0.1 W, 0603; Manufacturer: Vishay-Dale; CompType: Resistor; Value: 2.0k; Res_ohm: 2000; Value_Code: 2k00; Tolerance_%: 5; Power_W: 0.1; Value2: 0.1W; VDC_V: 75; TempCo: 200 ppm/C; SizeArea_mm2: 1.28; SizeX_mm: 1.6; SizeY_mm: 0.8; SizeZ_mm: 1; EIA_Code: E24; U/M: EA; AEC Category: Q200; Green_Lifecycle: Active; Green_REACh: Passed
R177 R187 = CRCW08050000Z0EA: as R176 on sheet TIDA-010011-E1_Processor_Power _Pg3
TP2 TP5 TP6 TP8 TP10 TP11 TP76 TP80 TP99 TP102 = 5000: as TP1 on sheet TIDA-010011-E1_Processor_Power _Pg3
TP4 TP7 TP9 TP101 = 5001: Test Point, Miniature, Black, TH; Manufacturer: Keystone; CompType: Test Point Loop; ContactFinish: Silver; Green_Lifecycle: Active; Green_REACh: Passed
TP48-TP50 TP100 = 5002: as TP47 on sheet TIDA-010011-E1_Processor_Power _Pg3
U1 = CMP-0014088-2: SIMPLE SWITCHER 4.5-V to 42-V Input, 2-A Power Module, RVQ00043A, RVQ0043A (B3QFN-43); Manufacturer: Texas Instruments; SizeX_mm: 10; CompType: IC; SizeZ_mm: 4.4; SizeArea_mm2: 100; SizeAreaWB_mm2: 144; U/M: EA
U2 = LMZ20502SILR: 2A Buck Simple Switcher Nano Module, SIL0008F; Alternate PartNumber: LMZ20502SILT; Manufacturer: Texas Instruments; SymbolCreator: a0411947; CompType: IC; U/M: EA
U3 = CMP-0066139-1: SIMPLE SWITCHER(R) 2.7V to 5.5V, 1A High Density Nano Module, SIL0008F (uSIP-8); Alternate PartNumber: LMZ20501SILT; Alternate Manufacturer: Texas Instruments; SizeAreaWB_mm2: 20.25; U/M: EA; SizeZ_mm: 1.75; SizeX_mm: 3.5; SizeArea_mm2: 12.25; CompType: IC
U7 = CMP-0065929-2: IC CONV DDR DDR2 DDR3 8SOPWRPAD; Alternate PartNumber: LP2998QMR/NOPB; Manufacturer: Texas Instruments; SizeZ_mm: 1.7; SizeX_mm: 5.0; SizeY_mm: 6.2; SizeArea_mm2: 31.0; U/M: EA; SizeAreaWB_mm2: 57.4
U9 = CMP-0013424-7: as U6 on sheet TIDA-010011-E1_Processor_Power _Pg3
U11 = CMP-0036438-3: Single Output LDO, 3 A, 2.375 to 3.5 V Input, with DDR Termination, 10-pin SON (DRC), -40 to 85 degC, Green (RoHS & no Sb/Br); Manufacturer: Texas Instruments; Vin(Min)(V): 2.3; Power Good: TRUE; Vin(Max)(V): 3.5; Rating: Catalog; SubFamily: Single Channel LDO; Iq(Typ)(mA): 0.5; Iout(Max)(A): 3; AEC Category: Q200; AEC Qualified: N; CompType: IC; SizeAreaWB_mm2: 16; SizeArea_mm2: 9; SizeZ_mm: 1
U36 = CMP-0051912-2: Dual Buffer Gate, DRL0006A, LARGE T&R; Manufacturer: Texas Instruments; F @ Nom Voltage(Max)(Mhz): 150; Rating: Catalog; Sub-Family: Non-Inverting Buffer/Driver; VCC(Min)(V): 1.65; Bits(#): 2; Logic: True; 3-State Output: No; Input Type: CMOS/TTL; Output Type: CMOS; Voltage(Nom)(V): 1.8,2.5,3.3,5; VCC(Max)(V): 5.5; Output Drive (IOL/IOH)(Max)(mA): 32/-32; tpd @ Nom Voltage(Max)(ns): 8.6,4.4,4.1,3.2; ICC @ Nom Voltage(Max)(mA): 0.01; Technology Family: LVC; AEC Category: Q200; AEC Qualified: N; CompType: IC; SizeArea_mm2: 2.56; SizeX_mm: 1.6; SizeZ_mm: 0.6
